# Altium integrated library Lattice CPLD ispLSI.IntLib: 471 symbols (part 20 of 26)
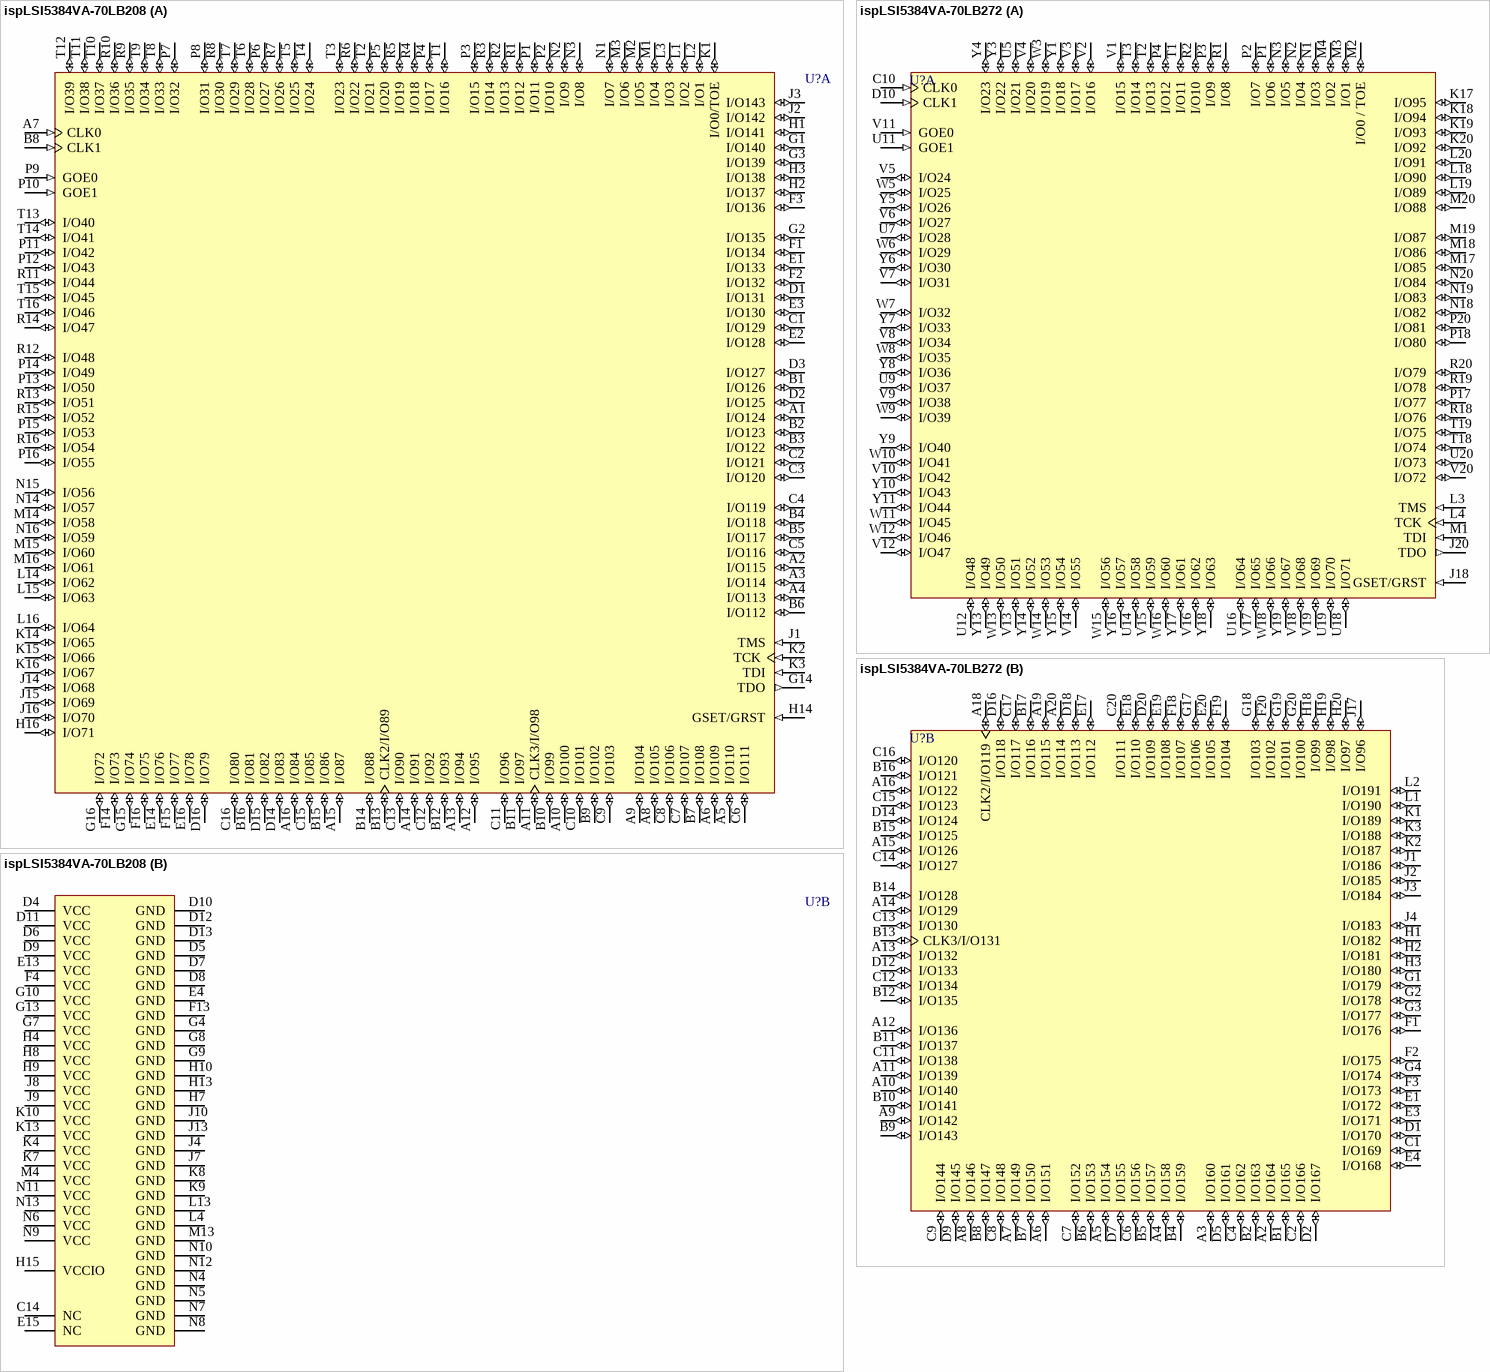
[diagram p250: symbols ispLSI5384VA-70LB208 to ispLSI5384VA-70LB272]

## ispLSI5384VA-70LB208
designator U?
In-System Programmable 3.3V SuperWIDE High Density PLD
footprint fpBGA208 (BGA, 208-Leads, Body 17x17mm, Pitch 1mm)
3D model 5256VA-fpBGA208 (208-Ball Fine Pitch Ball Grid Array (fpBGA208))
part A pins: A1 I/O124 (io), A2 I/O115 (io), A3 I/O114 (io), A4 I/O113 (io), A5 I/O110 (io), A6 I/O109 (io), A7 CLK0 (in), A8 I/O105 (io), A9 I/O104 (io), A10 I/O100 (io), A11 CLK3/I/O98 (io), A12 I/O95 (io), A13 I/O94 (io), A14 I/O91 (io), A15 I/O87 (io), A16 I/O84 (io), B1 I/O126 (io), B2 I/O123 (io), B3 I/O122 (io), B4 I/O118 (io), B5 I/O117 (io), B6 I/O112 (io), B7 I/O108 (io), B8 CLK1 (in), B9 I/O102 (io), B10 I/O99 (io), B11 I/O97 (io), B12 I/O93 (io), B13 CLK2/I/O89 (io), B14 I/O88 (io), B15 I/O86 (io), B16 I/O81 (io), C1 I/O129 (io), C2 I/O121 (io), C3 I/O120 (io), C4 I/O119 (io), C5 I/O116 (io), C6 I/O111 (io), C7 I/O107 (io), C8 I/O106 (io), C9 I/O103 (io), C10 I/O101 (io), C11 I/O96 (io), C12 I/O92 (io), C13 I/O90 (io), C15 I/O85 (io), C16 I/O80 (io), D1 I/O131 (io), D2 I/O125 (io), D3 I/O127 (io), D14 I/O83 (io), D15 I/O82 (io), D16 I/O79 (io), E1 I/O133 (io), E2 I/O128 (io), E3 I/O130 (io), E14 I/O76 (io), E16 I/O78 (io), F1 I/O134 (io), F2 I/O132 (io), F3 I/O136 (io), F14 I/O73 (io), F15 I/O77 (io), F16 I/O75 (io), G1 I/O140 (io), G2 I/O135 (io), G3 I/O139 (io), G14 TDO (out), G15 I/O74 (io), G16 I/O72 (io), H1 I/O141 (io), H2 I/O137 (io), H3 I/O138 (io), H14 GSET/GRST (in), H16 I/O71 (io), J1 TMS (in), J2 I/O142 (io), J3 I/O143 (io), J14 I/O68 (io), J15 I/O69 (io), J16 I/O70 (io), K1 I/O0/TOE (io), K2 TCK (in), K3 TDI (in), K14 I/O65 (io), K15 I/O66 (io), K16 I/O67 (io), L1 I/O2 (io), L2 I/O1 (io), L3 I/O3 (io), L14 I/O62 (io), L15 I/O63 (io), L16 I/O64 (io), M1 I/O4 (io), M2 I/O5 (io), M3 I/O6 (io), M14 I/O58 (io), M15 I/O60 (io), M16 I/O61 (io), N1 I/O7 (io), N2 I/O9 (io), N3 I/O8 (io), N14 I/O57 (io), N15 I/O56 (io), N16 I/O59 (io), P1 I/O11 (io), P2 I/O10 (io), P3 I/O15 (io), P4 I/O17 (io), P5 I/O20 (io), P6 I/O27 (io), P7 I/O32 (io), P8 I/O31 (io), P9 GOE0 (in), P10 GOE1 (in), P11 I/O42 (io), P12 I/O43 (io), P13 I/O50 (io), P14 I/O49 (io), P15 I/O53 (io), P16 I/O55 (io), R1 I/O12 (io), R2 I/O13 (io), R3 I/O14 (io), R4 I/O18 (io), R5 I/O19 (io), R6 I/O22 (io), R7 I/O26 (io), R8 I/O30 (io), R9 I/O35 (io), R10 I/O36 (io), R11 I/O44 (io), R12 I/O48 (io), R13 I/O51 (io), R14 I/O47 (io), R15 I/O52 (io), R16 I/O54 (io), T1 I/O16 (io), T2 I/O21 (io), T3 I/O23 (io), T4 I/O24 (io), T5 I/O25 (io), T6 I/O28 (io), T7 I/O29 (io), T8 I/O33 (io), T9 I/O34 (io), T10 I/O37 (io), T11 I/O38 (io), T12 I/O39 (io), T13 I/O40 (io), T14 I/O41 (io), T15 I/O45 (io), T16 I/O46 (io)
part B pins: C14 NC, D4 VCC (power), D5 GND (power), D6 VCC (power), D7 GND (power), D8 GND (power), D9 VCC (power), D10 GND (power), D11 VCC (power), D12 GND (power), D13 GND (power), E4 GND (power), E13 VCC (power), E15 NC, F4 VCC (power), F13 GND (power), G4 GND (power), G7 VCC (power), G8 GND (power), G9 GND (power), G10 VCC (power), G13 VCC (power), H4 VCC (power), H7 GND (power), H8 VCC (power), H9 VCC (power), H10 GND (power), H13 GND (power), H15 VCCIO (power), J4 GND (power), J7 GND (power), J8 VCC (power), J9 VCC (power), J10 GND (power), J13 GND (power), K4 VCC (power), K7 VCC (power), K8 GND (power), K9 GND (power), K10 VCC (power), K13 VCC (power), L4 GND (power), L13 GND (power), M4 VCC (power), M13 GND (power), N4 GND (power), N5 GND (power), N6 VCC (power), N7 GND (power), N8 GND (power), N9 VCC (power), N10 GND (power), N11 VCC (power), N12 GND (power), N13 VCC (power)

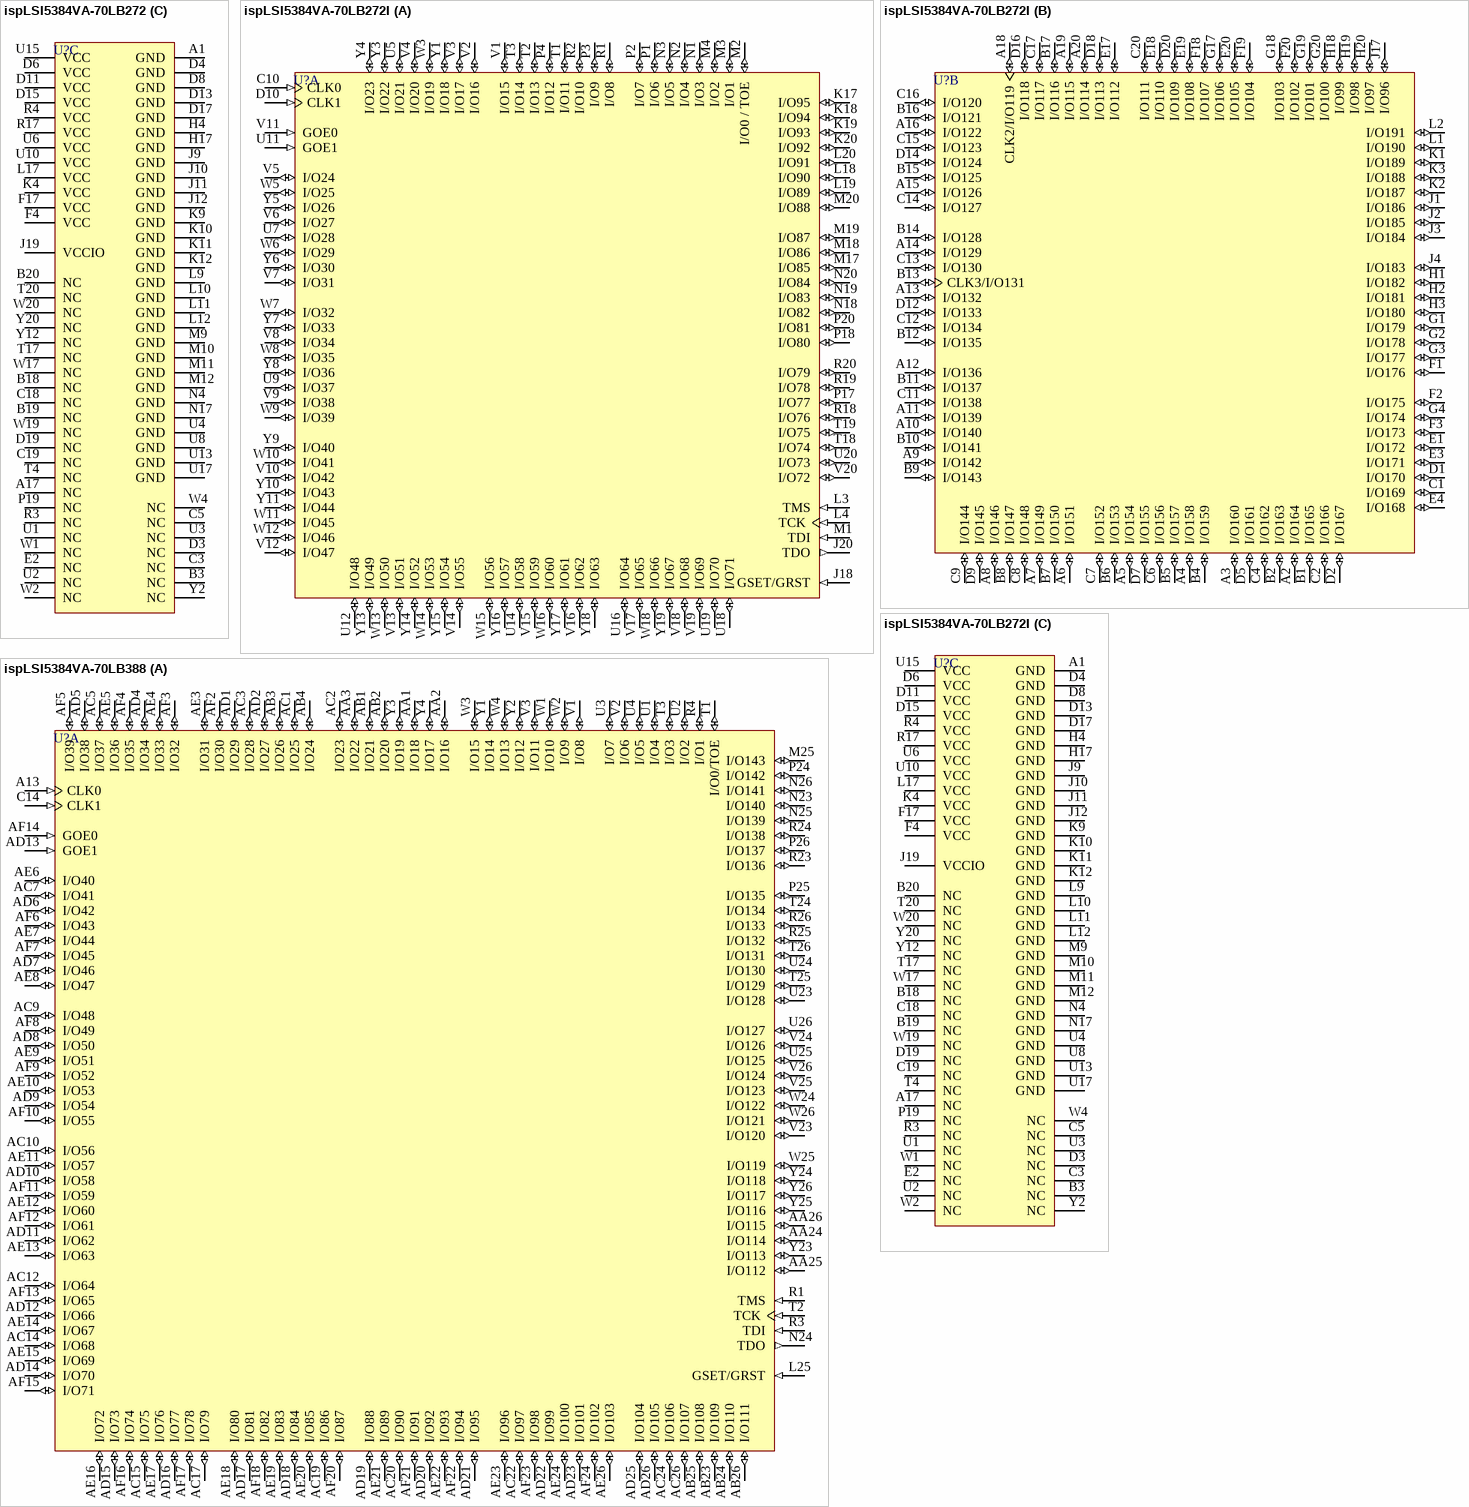
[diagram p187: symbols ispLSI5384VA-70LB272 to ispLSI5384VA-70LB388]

## ispLSI5384VA-70LB272
designator U?
In-System Programmable 3.3V SuperWIDE High Density PLD
footprint BGA272 (BGA, 272-Leads, Body 27x27mm, Pitch 1.27mm)
3D model 5384VA-BGA272 (272-Ball Ball Grid Array (BGA272))
part A pins: C10 CLK0 (in), D10 CLK1 (in), J18 GSET/GRST (in), J20 TDO (out), K17 I/O95 (io), K18 I/O94 (io), K19 I/O93 (io), K20 I/O92 (io), L3 TMS (in), L4 TCK (in), L18 I/O90 (io), L19 I/O89 (io), L20 I/O91 (io), M1 TDI (in), M2 I/O0 / TOE (io), M3 I/O1 (io), M4 I/O2 (io), M17 I/O85 (io), M18 I/O86 (io), M19 I/O87 (io), M20 I/O88 (io), N1 I/O3 (io), N2 I/O4 (io), N3 I/O5 (io), N18 I/O82 (io), N19 I/O83 (io), N20 I/O84 (io), P1 I/O6 (io), P2 I/O7 (io), P3 I/O9 (io), P4 I/O12 (io), P17 I/O77 (io), P18 I/O80 (io), P20 I/O81 (io), R1 I/O8 (io), R2 I/O10 (io), R18 I/O76 (io), R19 I/O78 (io), R20 I/O79 (io), T1 I/O11 (io), T2 I/O13 (io), T3 I/O14 (io), T18 I/O74 (io), T19 I/O75 (io), U5 I/O21 (io), U7 I/O28 (io), U9 I/O37 (io), U11 GOE1 (in), U12 I/O48 (io), U14 I/O58 (io), U16 I/O64 (io), U18 I/O71 (io), U19 I/O70 (io), U20 I/O73 (io), V1 I/O15 (io), V2 I/O16 (io), V3 I/O17 (io), V4 I/O20 (io), V5 I/O24 (io), V6 I/O27 (io), V7 I/O31 (io), V8 I/O34 (io), V9 I/O38 (io), V10 I/O42 (io), V11 GOE0 (in), V12 I/O47 (io), V13 I/O51 (io), V14 I/O55 (io), V15 I/O59 (io), V16 I/O62 (io), V17 I/O65 (io), V18 I/O68 (io), V19 I/O69 (io), V20 I/O72 (io), W3 I/O19 (io), W5 I/O25 (io), W6 I/O29 (io), W7 I/O32 (io), W8 I/O35 (io), W9 I/O39 (io), W10 I/O41 (io), W11 I/O45 (io), W12 I/O46 (io), W13 I/O50 (io), W14 I/O53 (io), W15 I/O56 (io), W16 I/O60 (io), W18 I/O66 (io), Y1 I/O18 (io), Y3 I/O22 (io), Y4 I/O23 (io), Y5 I/O26 (io), Y6 I/O30 (io), Y7 I/O33 (io), Y8 I/O36 (io), Y9 I/O40 (io), Y10 I/O43 (io), Y11 I/O44 (io), Y13 I/O49 (io), Y14 I/O52 (io), Y15 I/O54 (io), Y16 I/O57 (io), Y17 I/O61 (io), Y18 I/O63 (io), Y19 I/O67 (io)
part B pins: A2 I/O164 (io), A3 I/O160 (io), A4 I/O158 (io), A5 I/O154 (io), A6 I/O151 (io), A7 I/O149 (io), A8 I/O146 (io), A9 I/O142 (io), A10 I/O140 (io), A11 I/O139 (io), A12 I/O136 (io), A13 I/O132 (io), A14 I/O129 (io), A15 I/O126 (io), A16 I/O122 (io), A18 CLK2/I/O119 (io), A19 I/O115 (io), A20 I/O114 (io), B1 I/O165 (io), B2 I/O163 (io), B4 I/O159 (io), B5 I/O157 (io), B6 I/O153 (io), B7 I/O150 (io), B8 I/O147 (io), B9 I/O143 (io), B10 I/O141 (io), B11 I/O137 (io), B12 I/O135 (io), B13 CLK3/I/O131 (io), B14 I/O128 (io), B15 I/O125 (io), B16 I/O121 (io), B17 I/O116 (io), C1 I/O169 (io), C2 I/O166 (io), C4 I/O162 (io), C6 I/O156 (io), C7 I/O152 (io), C8 I/O148 (io), C9 I/O144 (io), C11 I/O138 (io), C12 I/O134 (io), C13 I/O130 (io), C14 I/O127 (io), C15 I/O123 (io), C16 I/O120 (io), C17 I/O117 (io), C20 I/O111 (io), D1 I/O170 (io), D2 I/O167 (io), D5 I/O161 (io), D7 I/O155 (io), D9 I/O145 (io), D12 I/O133 (io), D14 I/O124 (io), D16 I/O118 (io), D18 I/O113 (io), D20 I/O109 (io), E1 I/O172 (io), E3 I/O171 (io), E4 I/O168 (io), E17 I/O112 (io), E18 I/O110 (io), E19 I/O108 (io), E20 I/O105 (io), F1 I/O176 (io), F2 I/O175 (io), F3 I/O173 (io), F18 I/O107 (io), F19 I/O104 (io), F20 I/O102 (io), G1 I/O179 (io), G2 I/O178 (io), G3 I/O177 (io), G4 I/O174 (io), G17 I/O106 (io), G18 I/O103 (io), G19 I/O101 (io), G20 I/O100 (io), H1 I/O182 (io), H2 I/O181 (io), H3 I/O180 (io), H18 I/O99 (io), H19 I/O98 (io), H20 I/O97 (io), J1 I/O186 (io), J2 I/O185 (io), J3 I/O184 (io), J4 I/O183 (io), J17 I/O96 (io), K1 I/O189 (io), K2 I/O187 (io), K3 I/O188 (io), L1 I/O190 (io), L2 I/O191 (io)
part C pins: A1 GND (power), A17 NC, B3 NC, B18 NC, B19 NC, B20 NC, C3 NC, C5 NC, C18 NC, C19 NC, D3 NC, D4 GND (power), D6 VCC (power), D8 GND (power), D11 VCC (power), D13 GND (power), D15 VCC (power), D17 GND (power), D19 NC, E2 NC, F4 VCC (power), F17 VCC (power), H4 GND (power), H17 GND (power), J9 GND (power), J10 GND (power), J11 GND (power), J12 GND (power), J19 VCCIO (power), K4 VCC (power), K9 GND (power), K10 GND (power), K11 GND (power), K12 GND (power), L9 GND (power), L10 GND (power), L11 GND (power), L12 GND (power), L17 VCC (power), M9 GND (power), M10 GND (power), M11 GND (power), M12 GND (power), N4 GND (power), N17 GND (power), P19 NC, R3 NC, R4 VCC (power), R17 VCC (power), T4 NC, T17 NC, T20 NC, U1 NC, U2 NC, U3 NC, U4 GND (power), U6 VCC (power), U8 GND (power), U10 VCC (power), U13 GND (power), U15 VCC (power), U17 GND (power), W1 NC, W2 NC, W4 NC, W17 NC, W19 NC, W20 NC, Y2 NC, Y12 NC, Y20 NC

## ispLSI5384VA-70LB272I
designator U?
In-System Programmable 3.3V SuperWIDE High Density PLD
footprint BGA272 (BGA, 272-Leads, Body 27x27mm, Pitch 1.27mm)
3D model 5384VA-BGA272 (272-Ball Ball Grid Array (BGA272))
part A pins: C10 CLK0 (in), D10 CLK1 (in), J18 GSET/GRST (in), J20 TDO (out), K17 I/O95 (io), K18 I/O94 (io), K19 I/O93 (io), K20 I/O92 (io), L3 TMS (in), L4 TCK (in), L18 I/O90 (io), L19 I/O89 (io), L20 I/O91 (io), M1 TDI (in), M2 I/O0 / TOE (io), M3 I/O1 (io), M4 I/O2 (io), M17 I/O85 (io), M18 I/O86 (io), M19 I/O87 (io), M20 I/O88 (io), N1 I/O3 (io), N2 I/O4 (io), N3 I/O5 (io), N18 I/O82 (io), N19 I/O83 (io), N20 I/O84 (io), P1 I/O6 (io), P2 I/O7 (io), P3 I/O9 (io), P4 I/O12 (io), P17 I/O77 (io), P18 I/O80 (io), P20 I/O81 (io), R1 I/O8 (io), R2 I/O10 (io), R18 I/O76 (io), R19 I/O78 (io), R20 I/O79 (io), T1 I/O11 (io), T2 I/O13 (io), T3 I/O14 (io), T18 I/O74 (io), T19 I/O75 (io), U5 I/O21 (io), U7 I/O28 (io), U9 I/O37 (io), U11 GOE1 (in), U12 I/O48 (io), U14 I/O58 (io), U16 I/O64 (io), U18 I/O71 (io), U19 I/O70 (io), U20 I/O73 (io), V1 I/O15 (io), V2 I/O16 (io), V3 I/O17 (io), V4 I/O20 (io), V5 I/O24 (io), V6 I/O27 (io), V7 I/O31 (io), V8 I/O34 (io), V9 I/O38 (io), V10 I/O42 (io), V11 GOE0 (in), V12 I/O47 (io), V13 I/O51 (io), V14 I/O55 (io), V15 I/O59 (io), V16 I/O62 (io), V17 I/O65 (io), V18 I/O68 (io), V19 I/O69 (io), V20 I/O72 (io), W3 I/O19 (io), W5 I/O25 (io), W6 I/O29 (io), W7 I/O32 (io), W8 I/O35 (io), W9 I/O39 (io), W10 I/O41 (io), W11 I/O45 (io), W12 I/O46 (io), W13 I/O50 (io), W14 I/O53 (io), W15 I/O56 (io), W16 I/O60 (io), W18 I/O66 (io), Y1 I/O18 (io), Y3 I/O22 (io), Y4 I/O23 (io), Y5 I/O26 (io), Y6 I/O30 (io), Y7 I/O33 (io), Y8 I/O36 (io), Y9 I/O40 (io), Y10 I/O43 (io), Y11 I/O44 (io), Y13 I/O49 (io), Y14 I/O52 (io), Y15 I/O54 (io), Y16 I/O57 (io), Y17 I/O61 (io), Y18 I/O63 (io), Y19 I/O67 (io)
part B pins: A2 I/O164 (io), A3 I/O160 (io), A4 I/O158 (io), A5 I/O154 (io), A6 I/O151 (io), A7 I/O149 (io), A8 I/O146 (io), A9 I/O142 (io), A10 I/O140 (io), A11 I/O139 (io), A12 I/O136 (io), A13 I/O132 (io), A14 I/O129 (io), A15 I/O126 (io), A16 I/O122 (io), A18 CLK2/I/O119 (io), A19 I/O115 (io), A20 I/O114 (io), B1 I/O165 (io), B2 I/O163 (io), B4 I/O159 (io), B5 I/O157 (io), B6 I/O153 (io), B7 I/O150 (io), B8 I/O147 (io), B9 I/O143 (io), B10 I/O141 (io), B11 I/O137 (io), B12 I/O135 (io), B13 CLK3/I/O131 (io), B14 I/O128 (io), B15 I/O125 (io), B16 I/O121 (io), B17 I/O116 (io), C1 I/O169 (io), C2 I/O166 (io), C4 I/O162 (io), C6 I/O156 (io), C7 I/O152 (io), C8 I/O148 (io), C9 I/O144 (io), C11 I/O138 (io), C12 I/O134 (io), C13 I/O130 (io), C14 I/O127 (io), C15 I/O123 (io), C16 I/O120 (io), C17 I/O117 (io), C20 I/O111 (io), D1 I/O170 (io), D2 I/O167 (io), D5 I/O161 (io), D7 I/O155 (io), D9 I/O145 (io), D12 I/O133 (io), D14 I/O124 (io), D16 I/O118 (io), D18 I/O113 (io), D20 I/O109 (io), E1 I/O172 (io), E3 I/O171 (io), E4 I/O168 (io), E17 I/O112 (io), E18 I/O110 (io), E19 I/O108 (io), E20 I/O105 (io), F1 I/O176 (io), F2 I/O175 (io), F3 I/O173 (io), F18 I/O107 (io), F19 I/O104 (io), F20 I/O102 (io), G1 I/O179 (io), G2 I/O178 (io), G3 I/O177 (io), G4 I/O174 (io), G17 I/O106 (io), G18 I/O103 (io), G19 I/O101 (io), G20 I/O100 (io), H1 I/O182 (io), H2 I/O181 (io), H3 I/O180 (io), H18 I/O99 (io), H19 I/O98 (io), H20 I/O97 (io), J1 I/O186 (io), J2 I/O185 (io), J3 I/O184 (io), J4 I/O183 (io), J17 I/O96 (io), K1 I/O189 (io), K2 I/O187 (io), K3 I/O188 (io), L1 I/O190 (io), L2 I/O191 (io)
part C pins: A1 GND (power), A17 NC, B3 NC, B18 NC, B19 NC, B20 NC, C3 NC, C5 NC, C18 NC, C19 NC, D3 NC, D4 GND (power), D6 VCC (power), D8 GND (power), D11 VCC (power), D13 GND (power), D15 VCC (power), D17 GND (power), D19 NC, E2 NC, F4 VCC (power), F17 VCC (power), H4 GND (power), H17 GND (power), J9 GND (power), J10 GND (power), J11 GND (power), J12 GND (power), J19 VCCIO (power), K4 VCC (power), K9 GND (power), K10 GND (power), K11 GND (power), K12 GND (power), L9 GND (power), L10 GND (power), L11 GND (power), L12 GND (power), L17 VCC (power), M9 GND (power), M10 GND (power), M11 GND (power), M12 GND (power), N4 GND (power), N17 GND (power), P19 NC, R3 NC, R4 VCC (power), R17 VCC (power), T4 NC, T17 NC, T20 NC, U1 NC, U2 NC, U3 NC, U4 GND (power), U6 VCC (power), U8 GND (power), U10 VCC (power), U13 GND (power), U15 VCC (power), U17 GND (power), W1 NC, W2 NC, W4 NC, W17 NC, W19 NC, W20 NC, Y2 NC, Y12 NC, Y20 NC

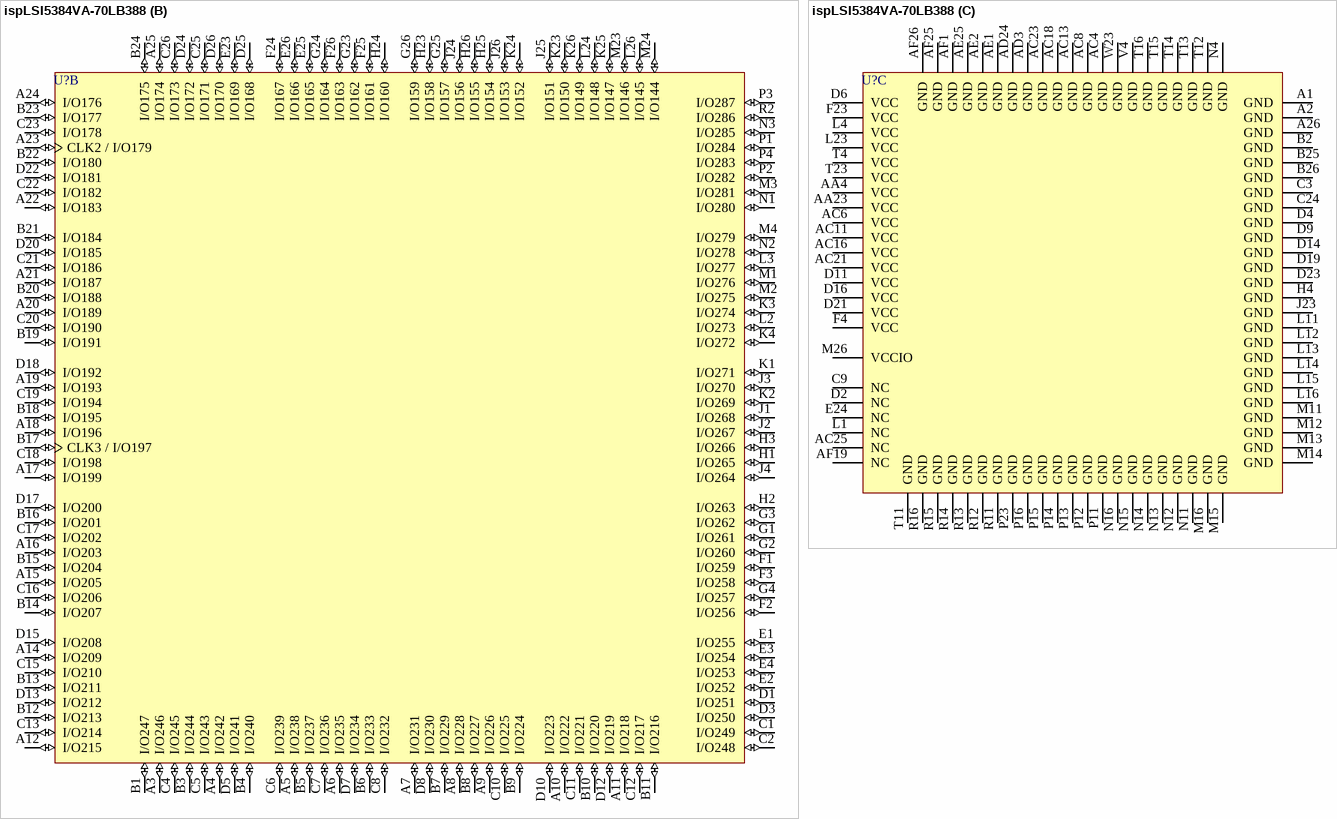
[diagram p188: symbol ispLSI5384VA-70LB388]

## ispLSI5384VA-70LB388
designator U?
In-System Programmable 3.3V SuperWIDE High Density PLD
footprint BGA388 (BGA, 388-Leads, Body 35x35mm, Pitch 1.27mm)
3D model 5384VA-BGA388 (388-Ball Ball Grid Array (BGA388))
part A pins: A13 CLK0 (in), AA1 I/O18 (io), AA2 I/O16 (io), AA3 I/O22 (io), AA24 I/O114 (io), AA25 I/O112 (io), AA26 I/O115 (io), AB1 I/O21 (io), AB2 I/O20 (io), AB3 I/O26 (io), AB4 I/O24 (io), AB23 I/O109 (io), AB24 I/O110 (io), AB25 I/O108 (io), AB26 I/O111 (io), AC1 I/O25 (io), AC2 I/O23 (io), AC3 I/O28 (io), AC5 I/O37 (io), AC7 I/O41 (io), AC9 I/O48 (io), AC10 I/O56 (io), AC12 I/O64 (io), AC14 I/O68 (io), AC15 I/O75 (io), AC17 I/O79 (io), AC19 I/O86 (io), AC20 I/O90 (io), AC22 I/O97 (io), AC24 I/O106 (io), AC26 I/O107 (io), AD1 I/O29 (io), AD2 I/O27 (io), AD4 I/O34 (io), AD5 I/O38 (io), AD6 I/O42 (io), AD7 I/O46 (io), AD8 I/O50 (io), AD9 I/O54 (io), AD10 I/O58 (io), AD11 I/O62 (io), AD12 I/O66 (io), AD13 GOE1 (in), AD14 I/O70 (io), AD15 I/O73 (io), AD16 I/O77 (io), AD17 I/O81 (io), AD18 I/O84 (io), AD19 I/O88 (io), AD20 I/O92 (io), AD21 I/O95 (io), AD22 I/O99 (io), AD23 I/O101 (io), AD25 I/O104 (io), AD26 I/O105 (io), AE3 I/O31 (io), AE4 I/O33 (io), AE5 I/O36 (io), AE6 I/O40 (io), AE7 I/O44 (io), AE8 I/O47 (io), AE9 I/O51 (io), AE10 I/O53 (io), AE11 I/O57 (io), AE12 I/O60 (io), AE13 I/O63 (io), AE14 I/O67 (io), AE15 I/O69 (io), AE16 I/O72 (io), AE17 I/O76 (io), AE18 I/O80 (io), AE19 I/O83 (io), AE20 I/O85 (io), AE21 I/O89 (io), AE22 I/O93 (io), AE23 I/O96 (io), AE24 I/O100 (io), AE26 I/O103 (io), AF2 I/O30 (io), AF3 I/O32 (io), AF4 I/O35 (io), AF5 I/O39 (io), AF6 I/O43 (io), AF7 I/O45 (io), AF8 I/O49 (io), AF9 I/O52 (io), AF10 I/O55 (io), AF11 I/O59 (io), AF12 I/O61 (io), AF13 I/O65 (io), AF14 GOE0 (in), AF15 I/O71 (io), AF16 I/O74 (io), AF17 I/O78 (io), AF18 I/O82 (io), AF20 I/O87 (io), AF21 I/O91 (io), AF22 I/O94 (io), AF23 I/O98 (io), AF24 I/O102 (io), C14 CLK1 (in), L25 GSET/GRST (in), M25 I/O143 (io), N23 I/O140 (io), N24 TDO (out), N25 I/O139 (io), N26 I/O141 (io), P24 I/O142 (io), P25 I/O135 (io), P26 I/O137 (io), R1 TMS (in), R3 TDI (in), R4 I/O1 (io), R23 I/O136 (io), R24 I/O138 (io), R25 I/O132 (io), R26 I/O133 (io), T1 I/O0/TOE (io), T2 TCK (in), T3 I/O3 (io), T24 I/O134 (io), T25 I/O129 (io), T26 I/O131 (io), U1 I/O4 (io), U2 I/O2 (io), U3 I/O7 (io), U4 I/O5 (io), U23 I/O128 (io), U24 I/O130 (io), U25 I/O125 (io), U26 I/O127 (io), V1 I/O8 (io), V2 I/O6 (io), V3 I/O11 (io), V23 I/O120 (io), V24 I/O126 (io), V25 I/O123 (io), V26 I/O124 (io), W1 I/O10 (io), W2 I/O9 (io), W3 I/O15 (io), W4 I/O13 (io), W24 I/O122 (io), W25 I/O119 (io), W26 I/O121 (io), Y1 I/O14 (io), Y2 I/O12 (io), Y3 I/O19 (io), Y4 I/O17 (io), Y23 I/O113 (io), Y24 I/O118 (io), Y25 I/O116 (io), Y26 I/O117 (io)
part B pins: A3 I/O246 (io), A4 I/O242 (io), A5 I/O238 (io), A6 I/O235 (io), A7 I/O231 (io), A8 I/O228 (io), A9 I/O226 (io), A10 I/O222 (io), A11 I/O218 (io), A12 I/O215 (io), A14 I/O209 (io), A15 I/O205 (io), A16 I/O203 (io), A17 I/O199 (io), A18 I/O196 (io), A19 I/O193 (io), A20 I/O189 (io), A21 I/O187 (io), A22 I/O183 (io), A23 CLK2 / I/O179 (io), A24 I/O176 (io), A25 I/O174 (io), B1 I/O247 (io), B3 I/O244 (io), B4 I/O240 (io), B5 I/O237 (io), B6 I/O233 (io), B7 I/O229 (io), B8 I/O227 (io), B9 I/O224 (io), B10 I/O220 (io), B11 I/O216 (io), B12 I/O213 (io), B13 I/O211 (io), B14 I/O207 (io), B15 I/O204 (io), B16 I/O201 (io), B17 CLK3 / I/O197 (io), B18 I/O195 (io), B19 I/O191 (io), B20 I/O188 (io), B21 I/O184 (io), B22 I/O180 (io), B23 I/O177 (io), B24 I/O175 (io), C1 I/O249 (io), C2 I/O248 (io), C4 I/O245 (io), C5 I/O243 (io), C6 I/O239 (io), C7 I/O236 (io), C8 I/O232 (io), C10 I/O225 (io), C11 I/O221 (io), C12 I/O217 (io), C13 I/O214 (io), C15 I/O210 (io), C16 I/O206 (io), C17 I/O202 (io), C18 I/O198 (io), C19 I/O194 (io), C20 I/O190 (io), C21 I/O186 (io), C22 I/O182 (io), C23 I/O178 (io), C25 I/O171 (io), C26 I/O173 (io), D1 I/O251 (io), D3 I/O250 (io), D5 I/O241 (io), D7 I/O234 (io), D8 I/O230 (io), D10 I/O223 (io), D12 I/O219 (io), D13 I/O212 (io), D15 I/O208 (io), D17 I/O200 (io), D18 I/O192 (io), D20 I/O185 (io), D22 I/O181 (io), D24 I/O172 (io), D25 I/O168 (io), D26 I/O170 (io), E1 I/O255 (io), E2 I/O252 (io), E3 I/O254 (io), E4 I/O253 (io), E23 I/O169 (io), E25 I/O165 (io), E26 I/O166 (io), F1 I/O259 (io), F2 I/O256 (io), F3 I/O258 (io), F24 I/O167 (io), F25 I/O161 (io), F26 I/O163 (io), G1 I/O261 (io), G2 I/O260 (io), G3 I/O262 (io), G4 I/O257 (io), G23 I/O162 (io), G24 I/O164 (io), G25 I/O157 (io), G26 I/O159 (io), H1 I/O265 (io), H2 I/O263 (io), H3 I/O266 (io), H23 I/O158 (io), H24 I/O160 (io), H25 I/O154 (io), H26 I/O155 (io), J1 I/O268 (io), J2 I/O267 (io), J3 I/O270 (io), J4 I/O264 (io), J24 I/O156 (io), J25 I/O151 (io), J26 I/O153 (io), K1 I/O271 (io), K2 I/O269 (io), K3 I/O274 (io), K4 I/O272 (io), K23 I/O150 (io), K24 I/O152 (io), K25 I/O147 (io), K26 I/O149 (io), L2 I/O273 (io), L3 I/O277 (io), L24 I/O148 (io), L26 I/O145 (io), M1 I/O276 (io), M2 I/O275 (io), M3 I/O281 (io), M4 I/O279 (io), M23 I/O146 (io), M24 I/O144 (io), N1 I/O280 (io), N2 I/O278 (io), N3 I/O285 (io), P1 I/O284 (io), P2 I/O282 (io), P3 I/O287 (io), P4 I/O283 (io), R2 I/O286 (io)
part C pins: A1 GND (power), A2 GND (power), A26 GND (power), AA4 VCC (power), AA23 VCC (power), AC4 GND (power), AC6 VCC (power), AC8 GND (power), AC11 VCC (power), AC13 GND (power), AC16 VCC (power), AC18 GND (power), AC21 VCC (power), AC23 GND (power), AC25 NC, AD3 GND (power), AD24 GND (power), AE1 GND (power), AE2 GND (power), AE25 GND (power), AF1 GND (power), AF19 NC, AF25 GND (power), AF26 GND (power), B2 GND (power), B25 GND (power), B26 GND (power), C3 GND (power), C9 NC, C24 GND (power), D2 NC, D4 GND (power), D6 VCC (power), D9 GND (power), D11 VCC (power), D14 GND (power), D16 VCC (power), D19 GND (power), D21 VCC (power), D23 GND (power), E24 NC, F4 VCC (power), F23 VCC (power), H4 GND (power), J23 GND (power), L1 NC, L4 VCC (power), L11 GND (power), L12 GND (power), L13 GND (power), L14 GND (power), L15 GND (power), L16 GND (power), L23 VCC (power), M11 GND (power), M12 GND (power), M13 GND (power), M14 GND (power), M15 GND (power), M16 GND (power), M26 VCCIO (power), N4 GND (power), N11 GND (power), N12 GND (power), N13 GND (power), N14 GND (power), N15 GND (power), N16 GND (power), P11 GND (power), P12 GND (power), P13 GND (power), P14 GND (power), P15 GND (power), P16 GND (power), P23 GND (power), R11 GND (power), R12 GND (power), R13 GND (power), R14 GND (power), R15 GND (power), R16 GND (power), T4 VCC (power), T11 GND (power), T12 GND (power), T13 GND (power), T14 GND (power), T15 GND (power), T16 GND (power), T23 VCC (power), V4 GND (power), W23 GND (power)

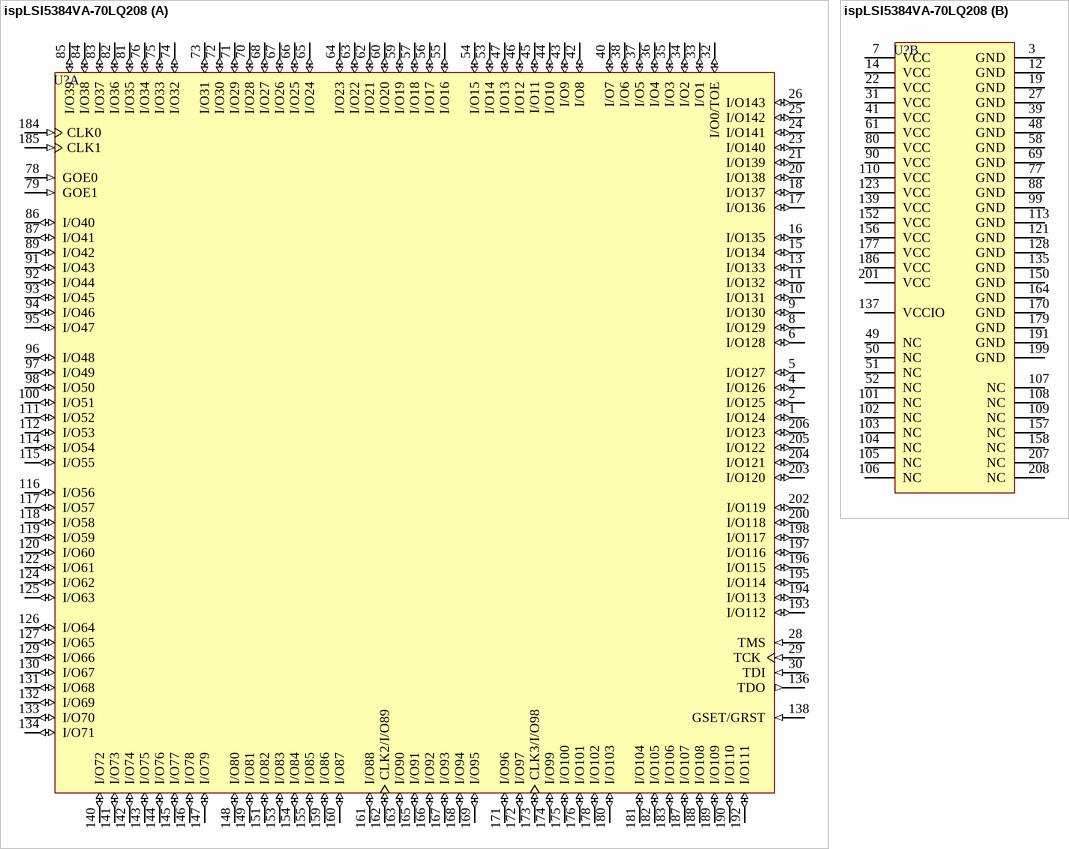
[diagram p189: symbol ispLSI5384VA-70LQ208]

## ispLSI5384VA-70LQ208
designator U?
In-System Programmable 3.3V SuperWIDE High Density PLD
footprint PQFP208_N (Shrink QFP, 208-Leads, Body 28x28mm, Pitch 0.5mm, IPC Medium Density)
footprint PQFP208_L (Shrink QFP, 208-Leads, Body 28x28mm, Pitch 0.5mm, IPC High Density)
footprint PQFP208_M (Shrink QFP, 208-Leads, Body 28x28mm, Pitch 0.5mm, IPC Low Density)
3D model 5384VA-PQFP208 (208-Pin Plastic Quad Flat Pack (PQFP208))
part A pins: 1 I/O124 (io), 2 I/O125 (io), 4 I/O126 (io), 5 I/O127 (io), 6 I/O128 (io), 8 I/O129 (io), 9 I/O130 (io), 10 I/O131 (io), 11 I/O132 (io), 13 I/O133 (io), 15 I/O134 (io), 16 I/O135 (io), 17 I/O136 (io), 18 I/O137 (io), 20 I/O138 (io), 21 I/O139 (io), 23 I/O140 (io), 24 I/O141 (io), 25 I/O142 (io), 26 I/O143 (io), 28 TMS (in), 29 TCK (in), 30 TDI (in), 32 I/O0/TOE (io), 33 I/O1 (io), 34 I/O2 (io), 35 I/O3 (io), 36 I/O4 (io), 37 I/O5 (io), 38 I/O6 (io), 40 I/O7 (io), 42 I/O8 (io), 43 I/O9 (io), 44 I/O10 (io), 45 I/O11 (io), 46 I/O12 (io), 47 I/O13 (io), 53 I/O14 (io), 54 I/O15 (io), 55 I/O16 (io), 56 I/O17 (io), 57 I/O18 (io), 59 I/O19 (io), 60 I/O20 (io), 62 I/O21 (io), 63 I/O22 (io), 64 I/O23 (io), 65 I/O24 (io), 66 I/O25 (io), 67 I/O26 (io), 68 I/O27 (io), 70 I/O28 (io), 71 I/O29 (io), 72 I/O30 (io), 73 I/O31 (io), 74 I/O32 (io), 75 I/O33 (io), 76 I/O34 (io), 78 GOE0 (in), 79 GOE1 (in), 81 I/O35 (io), 82 I/O36 (io), 83 I/O37 (io), 84 I/O38 (io), 85 I/O39 (io), 86 I/O40 (io), 87 I/O41 (io), 89 I/O42 (io), 91 I/O43 (io), 92 I/O44 (io), 93 I/O45 (io), 94 I/O46 (io), 95 I/O47 (io), 96 I/O48 (io), 97 I/O49 (io), 98 I/O50 (io), 100 I/O51 (io), 111 I/O52 (io), 112 I/O53 (io), 114 I/O54 (io), 115 I/O55 (io), 116 I/O56 (io), 117 I/O57 (io), 118 I/O58 (io), 119 I/O59 (io), 120 I/O60 (io), 122 I/O61 (io), 124 I/O62 (io), 125 I/O63 (io), 126 I/O64 (io), 127 I/O65 (io), 129 I/O66 (io), 130 I/O67 (io), 131 I/O68 (io), 132 I/O69 (io), 133 I/O70 (io), 134 I/O71 (io), 136 TDO (out), 138 GSET/GRST (in), 140 I/O72 (io), 141 I/O73 (io), 142 I/O74 (io), 143 I/O75 (io), 144 I/O76 (io), 145 I/O77 (io), 146 I/O78 (io), 147 I/O79 (io), 148 I/O80 (io), 149 I/O81 (io), 151 I/O82 (io), 153 I/O83 (io), 154 I/O84 (io), 155 I/O85 (io), 159 I/O86 (io), 160 I/O87 (io), 161 I/O88 (io), 162 CLK2/I/O89 (io), 163 I/O90 (io), 165 I/O91 (io), 166 I/O92 (io), 167 I/O93 (io), 168 I/O94 (io), 169 I/O95 (io), 171 I/O96 (io), 172 I/O97 (io), 173 CLK3/I/O98 (io), 174 I/O99 (io), 175 I/O100 (io), 176 I/O101 (io), 178 I/O102 (io), 180 I/O103 (io), 181 I/O104 (io), 182 I/O105 (io), 183 I/O106 (io), 184 CLK0 (in), 185 CLK1 (in), 187 I/O107 (io), 188 I/O108 (io), 189 I/O109 (io), 190 I/O110 (io), 192 I/O111 (io), 193 I/O112 (io), 194 I/O113 (io), 195 I/O114 (io), 196 I/O115 (io), 197 I/O116 (io), 198 I/O117 (io), 200 I/O118 (io), 202 I/O119 (io), 203 I/O120 (io), 204 I/O121 (io), 205 I/O122 (io), 206 I/O123 (io)
part B pins: 3 GND (power), 7 VCC (power), 12 GND (power), 14 VCC (power), 19 GND (power), 22 VCC (power), 27 GND (power), 31 VCC (power), 39 GND (power), 41 VCC (power), 48 GND (power), 49 NC, 50 NC, 51 NC, 52 NC, 58 GND (power), 61 VCC (power), 69 GND (power), 77 GND (power), 80 VCC (power), 88 GND (power), 90 VCC (power), 99 GND (power), 101 NC, 102 NC, 103 NC, 104 NC, 105 NC, 106 NC, 107 NC, 108 NC, 109 NC, 110 VCC (power), 113 GND (power), 121 GND (power), 123 VCC (power), 128 GND (power), 135 GND (power), 137 VCCIO (power), 139 VCC (power), 150 GND (power), 152 VCC (power), 156 VCC (power), 157 NC, 158 NC, 164 GND (power), 170 GND (power), 177 VCC (power), 179 GND (power), 186 VCC (power), 191 GND (power), 199 GND (power), 201 VCC (power), 207 NC, 208 NC

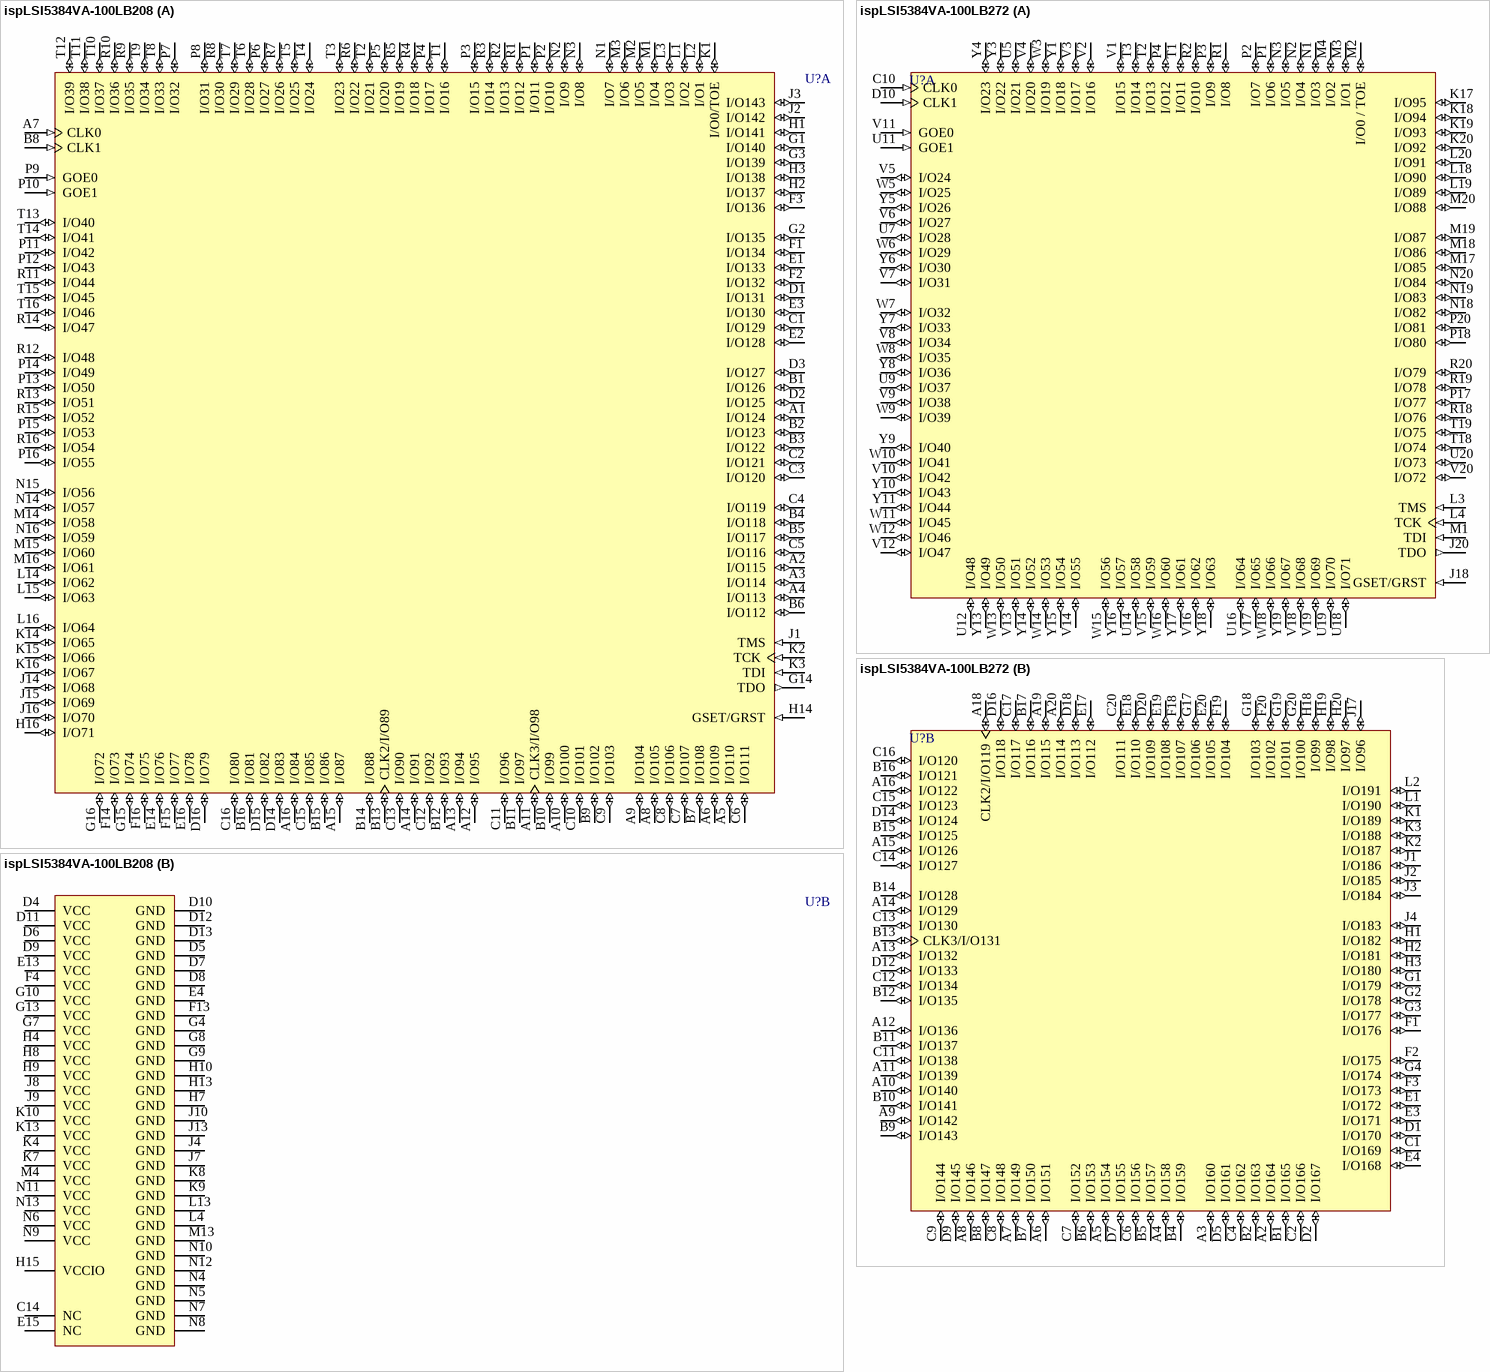
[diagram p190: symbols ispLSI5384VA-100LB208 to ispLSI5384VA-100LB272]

## ispLSI5384VA-100LB208
designator U?
In-System Programmable 3.3V SuperWIDE High Density PLD
footprint fpBGA208 (BGA, 208-Leads, Body 17x17mm, Pitch 1mm)
3D model 5256VA-fpBGA208 (208-Ball Fine Pitch Ball Grid Array (fpBGA208))
part A pins: A1 I/O124 (io), A2 I/O115 (io), A3 I/O114 (io), A4 I/O113 (io), A5 I/O110 (io), A6 I/O109 (io), A7 CLK0 (in), A8 I/O105 (io), A9 I/O104 (io), A10 I/O100 (io), A11 CLK3/I/O98 (io), A12 I/O95 (io), A13 I/O94 (io), A14 I/O91 (io), A15 I/O87 (io), A16 I/O84 (io), B1 I/O126 (io), B2 I/O123 (io), B3 I/O122 (io), B4 I/O118 (io), B5 I/O117 (io), B6 I/O112 (io), B7 I/O108 (io), B8 CLK1 (in), B9 I/O102 (io), B10 I/O99 (io), B11 I/O97 (io), B12 I/O93 (io), B13 CLK2/I/O89 (io), B14 I/O88 (io), B15 I/O86 (io), B16 I/O81 (io), C1 I/O129 (io), C2 I/O121 (io), C3 I/O120 (io), C4 I/O119 (io), C5 I/O116 (io), C6 I/O111 (io), C7 I/O107 (io), C8 I/O106 (io), C9 I/O103 (io), C10 I/O101 (io), C11 I/O96 (io), C12 I/O92 (io), C13 I/O90 (io), C15 I/O85 (io), C16 I/O80 (io), D1 I/O131 (io), D2 I/O125 (io), D3 I/O127 (io), D14 I/O83 (io), D15 I/O82 (io), D16 I/O79 (io), E1 I/O133 (io), E2 I/O128 (io), E3 I/O130 (io), E14 I/O76 (io), E16 I/O78 (io), F1 I/O134 (io), F2 I/O132 (io), F3 I/O136 (io), F14 I/O73 (io), F15 I/O77 (io), F16 I/O75 (io), G1 I/O140 (io), G2 I/O135 (io), G3 I/O139 (io), G14 TDO (out), G15 I/O74 (io), G16 I/O72 (io), H1 I/O141 (io), H2 I/O137 (io), H3 I/O138 (io), H14 GSET/GRST (in), H16 I/O71 (io), J1 TMS (in), J2 I/O142 (io), J3 I/O143 (io), J14 I/O68 (io), J15 I/O69 (io), J16 I/O70 (io), K1 I/O0/TOE (io), K2 TCK (in), K3 TDI (in), K14 I/O65 (io), K15 I/O66 (io), K16 I/O67 (io), L1 I/O2 (io), L2 I/O1 (io), L3 I/O3 (io), L14 I/O62 (io), L15 I/O63 (io), L16 I/O64 (io), M1 I/O4 (io), M2 I/O5 (io), M3 I/O6 (io), M14 I/O58 (io), M15 I/O60 (io), M16 I/O61 (io), N1 I/O7 (io), N2 I/O9 (io), N3 I/O8 (io), N14 I/O57 (io), N15 I/O56 (io), N16 I/O59 (io), P1 I/O11 (io), P2 I/O10 (io), P3 I/O15 (io), P4 I/O17 (io), P5 I/O20 (io), P6 I/O27 (io), P7 I/O32 (io), P8 I/O31 (io), P9 GOE0 (in), P10 GOE1 (in), P11 I/O42 (io), P12 I/O43 (io), P13 I/O50 (io), P14 I/O49 (io), P15 I/O53 (io), P16 I/O55 (io), R1 I/O12 (io), R2 I/O13 (io), R3 I/O14 (io), R4 I/O18 (io), R5 I/O19 (io), R6 I/O22 (io), R7 I/O26 (io), R8 I/O30 (io), R9 I/O35 (io), R10 I/O36 (io), R11 I/O44 (io), R12 I/O48 (io), R13 I/O51 (io), R14 I/O47 (io), R15 I/O52 (io), R16 I/O54 (io), T1 I/O16 (io), T2 I/O21 (io), T3 I/O23 (io), T4 I/O24 (io), T5 I/O25 (io), T6 I/O28 (io), T7 I/O29 (io), T8 I/O33 (io), T9 I/O34 (io), T10 I/O37 (io), T11 I/O38 (io), T12 I/O39 (io), T13 I/O40 (io), T14 I/O41 (io), T15 I/O45 (io), T16 I/O46 (io)
part B pins: C14 NC, D4 VCC (power), D5 GND (power), D6 VCC (power), D7 GND (power), D8 GND (power), D9 VCC (power), D10 GND (power), D11 VCC (power), D12 GND (power), D13 GND (power), E4 GND (power), E13 VCC (power), E15 NC, F4 VCC (power), F13 GND (power), G4 GND (power), G7 VCC (power), G8 GND (power), G9 GND (power), G10 VCC (power), G13 VCC (power), H4 VCC (power), H7 GND (power), H8 VCC (power), H9 VCC (power), H10 GND (power), H13 GND (power), H15 VCCIO (power), J4 GND (power), J7 GND (power), J8 VCC (power), J9 VCC (power), J10 GND (power), J13 GND (power), K4 VCC (power), K7 VCC (power), K8 GND (power), K9 GND (power), K10 VCC (power), K13 VCC (power), L4 GND (power), L13 GND (power), M4 VCC (power), M13 GND (power), N4 GND (power), N5 GND (power), N6 VCC (power), N7 GND (power), N8 GND (power), N9 VCC (power), N10 GND (power), N11 VCC (power), N12 GND (power), N13 VCC (power)

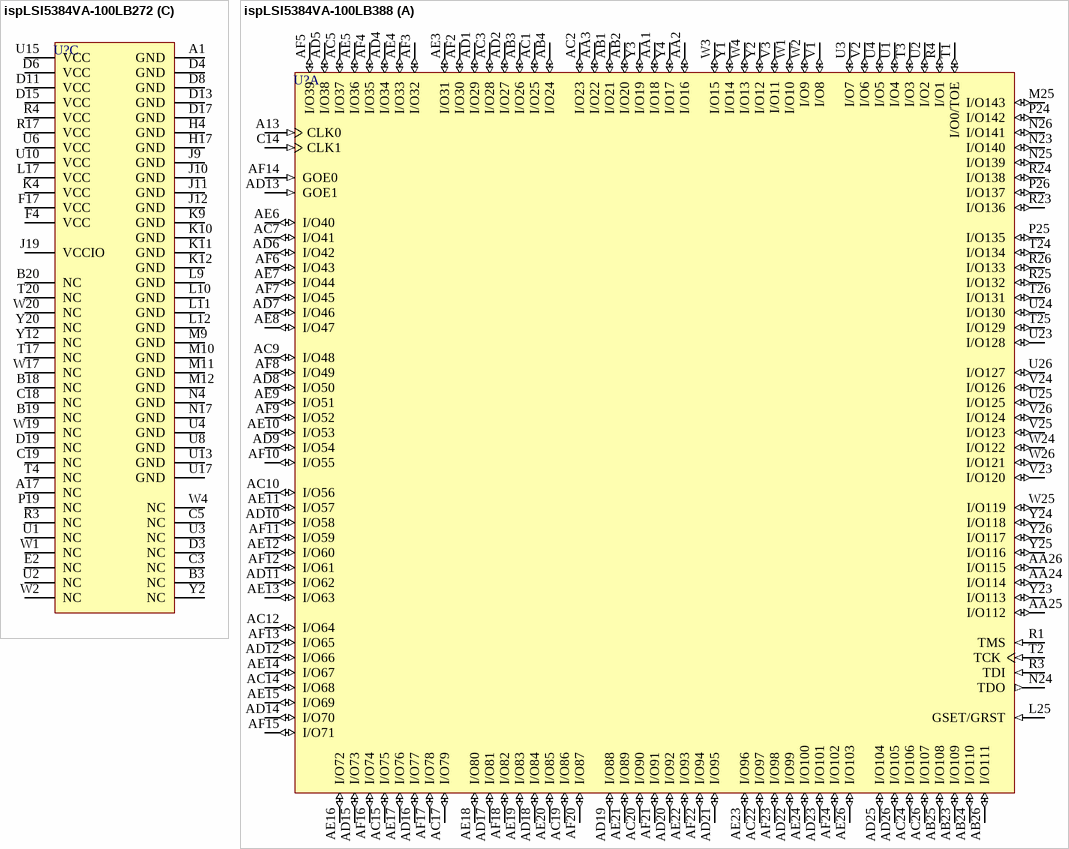
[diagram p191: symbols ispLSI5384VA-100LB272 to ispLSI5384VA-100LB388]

## ispLSI5384VA-100LB272
designator U?
In-System Programmable 3.3V SuperWIDE High Density PLD
footprint BGA272 (BGA, 272-Leads, Body 27x27mm, Pitch 1.27mm)
3D model 5384VA-BGA272 (272-Ball Ball Grid Array (BGA272))
part A pins: C10 CLK0 (in), D10 CLK1 (in), J18 GSET/GRST (in), J20 TDO (out), K17 I/O95 (io), K18 I/O94 (io), K19 I/O93 (io), K20 I/O92 (io), L3 TMS (in), L4 TCK (in), L18 I/O90 (io), L19 I/O89 (io), L20 I/O91 (io), M1 TDI (in), M2 I/O0 / TOE (io), M3 I/O1 (io), M4 I/O2 (io), M17 I/O85 (io), M18 I/O86 (io), M19 I/O87 (io), M20 I/O88 (io), N1 I/O3 (io), N2 I/O4 (io), N3 I/O5 (io), N18 I/O82 (io), N19 I/O83 (io), N20 I/O84 (io), P1 I/O6 (io), P2 I/O7 (io), P3 I/O9 (io), P4 I/O12 (io), P17 I/O77 (io), P18 I/O80 (io), P20 I/O81 (io), R1 I/O8 (io), R2 I/O10 (io), R18 I/O76 (io), R19 I/O78 (io), R20 I/O79 (io), T1 I/O11 (io), T2 I/O13 (io), T3 I/O14 (io), T18 I/O74 (io), T19 I/O75 (io), U5 I/O21 (io), U7 I/O28 (io), U9 I/O37 (io), U11 GOE1 (in), U12 I/O48 (io), U14 I/O58 (io), U16 I/O64 (io), U18 I/O71 (io), U19 I/O70 (io), U20 I/O73 (io), V1 I/O15 (io), V2 I/O16 (io), V3 I/O17 (io), V4 I/O20 (io), V5 I/O24 (io), V6 I/O27 (io), V7 I/O31 (io), V8 I/O34 (io), V9 I/O38 (io), V10 I/O42 (io), V11 GOE0 (in), V12 I/O47 (io), V13 I/O51 (io), V14 I/O55 (io), V15 I/O59 (io), V16 I/O62 (io), V17 I/O65 (io), V18 I/O68 (io), V19 I/O69 (io), V20 I/O72 (io), W3 I/O19 (io), W5 I/O25 (io), W6 I/O29 (io), W7 I/O32 (io), W8 I/O35 (io), W9 I/O39 (io), W10 I/O41 (io), W11 I/O45 (io), W12 I/O46 (io), W13 I/O50 (io), W14 I/O53 (io), W15 I/O56 (io), W16 I/O60 (io), W18 I/O66 (io), Y1 I/O18 (io), Y3 I/O22 (io), Y4 I/O23 (io), Y5 I/O26 (io), Y6 I/O30 (io), Y7 I/O33 (io), Y8 I/O36 (io), Y9 I/O40 (io), Y10 I/O43 (io), Y11 I/O44 (io), Y13 I/O49 (io), Y14 I/O52 (io), Y15 I/O54 (io), Y16 I/O57 (io), Y17 I/O61 (io), Y18 I/O63 (io), Y19 I/O67 (io)
part B pins: A2 I/O164 (io), A3 I/O160 (io), A4 I/O158 (io), A5 I/O154 (io), A6 I/O151 (io), A7 I/O149 (io), A8 I/O146 (io), A9 I/O142 (io), A10 I/O140 (io), A11 I/O139 (io), A12 I/O136 (io), A13 I/O132 (io), A14 I/O129 (io), A15 I/O126 (io), A16 I/O122 (io), A18 CLK2/I/O119 (io), A19 I/O115 (io), A20 I/O114 (io), B1 I/O165 (io), B2 I/O163 (io), B4 I/O159 (io), B5 I/O157 (io), B6 I/O153 (io), B7 I/O150 (io), B8 I/O147 (io), B9 I/O143 (io), B10 I/O141 (io), B11 I/O137 (io), B12 I/O135 (io), B13 CLK3/I/O131 (io), B14 I/O128 (io), B15 I/O125 (io), B16 I/O121 (io), B17 I/O116 (io), C1 I/O169 (io), C2 I/O166 (io), C4 I/O162 (io), C6 I/O156 (io), C7 I/O152 (io), C8 I/O148 (io), C9 I/O144 (io), C11 I/O138 (io), C12 I/O134 (io), C13 I/O130 (io), C14 I/O127 (io), C15 I/O123 (io), C16 I/O120 (io), C17 I/O117 (io), C20 I/O111 (io), D1 I/O170 (io), D2 I/O167 (io), D5 I/O161 (io), D7 I/O155 (io), D9 I/O145 (io), D12 I/O133 (io), D14 I/O124 (io), D16 I/O118 (io), D18 I/O113 (io), D20 I/O109 (io), E1 I/O172 (io), E3 I/O171 (io), E4 I/O168 (io), E17 I/O112 (io), E18 I/O110 (io), E19 I/O108 (io), E20 I/O105 (io), F1 I/O176 (io), F2 I/O175 (io), F3 I/O173 (io), F18 I/O107 (io), F19 I/O104 (io), F20 I/O102 (io), G1 I/O179 (io), G2 I/O178 (io), G3 I/O177 (io), G4 I/O174 (io), G17 I/O106 (io), G18 I/O103 (io), G19 I/O101 (io), G20 I/O100 (io), H1 I/O182 (io), H2 I/O181 (io), H3 I/O180 (io), H18 I/O99 (io), H19 I/O98 (io), H20 I/O97 (io), J1 I/O186 (io), J2 I/O185 (io), J3 I/O184 (io), J4 I/O183 (io), J17 I/O96 (io), K1 I/O189 (io), K2 I/O187 (io), K3 I/O188 (io), L1 I/O190 (io), L2 I/O191 (io)
part C pins: A1 GND (power), A17 NC, B3 NC, B18 NC, B19 NC, B20 NC, C3 NC, C5 NC, C18 NC, C19 NC, D3 NC, D4 GND (power), D6 VCC (power), D8 GND (power), D11 VCC (power), D13 GND (power), D15 VCC (power), D17 GND (power), D19 NC, E2 NC, F4 VCC (power), F17 VCC (power), H4 GND (power), H17 GND (power), J9 GND (power), J10 GND (power), J11 GND (power), J12 GND (power), J19 VCCIO (power), K4 VCC (power), K9 GND (power), K10 GND (power), K11 GND (power), K12 GND (power), L9 GND (power), L10 GND (power), L11 GND (power), L12 GND (power), L17 VCC (power), M9 GND (power), M10 GND (power), M11 GND (power), M12 GND (power), N4 GND (power), N17 GND (power), P19 NC, R3 NC, R4 VCC (power), R17 VCC (power), T4 NC, T17 NC, T20 NC, U1 NC, U2 NC, U3 NC, U4 GND (power), U6 VCC (power), U8 GND (power), U10 VCC (power), U13 GND (power), U15 VCC (power), U17 GND (power), W1 NC, W2 NC, W4 NC, W17 NC, W19 NC, W20 NC, Y2 NC, Y12 NC, Y20 NC

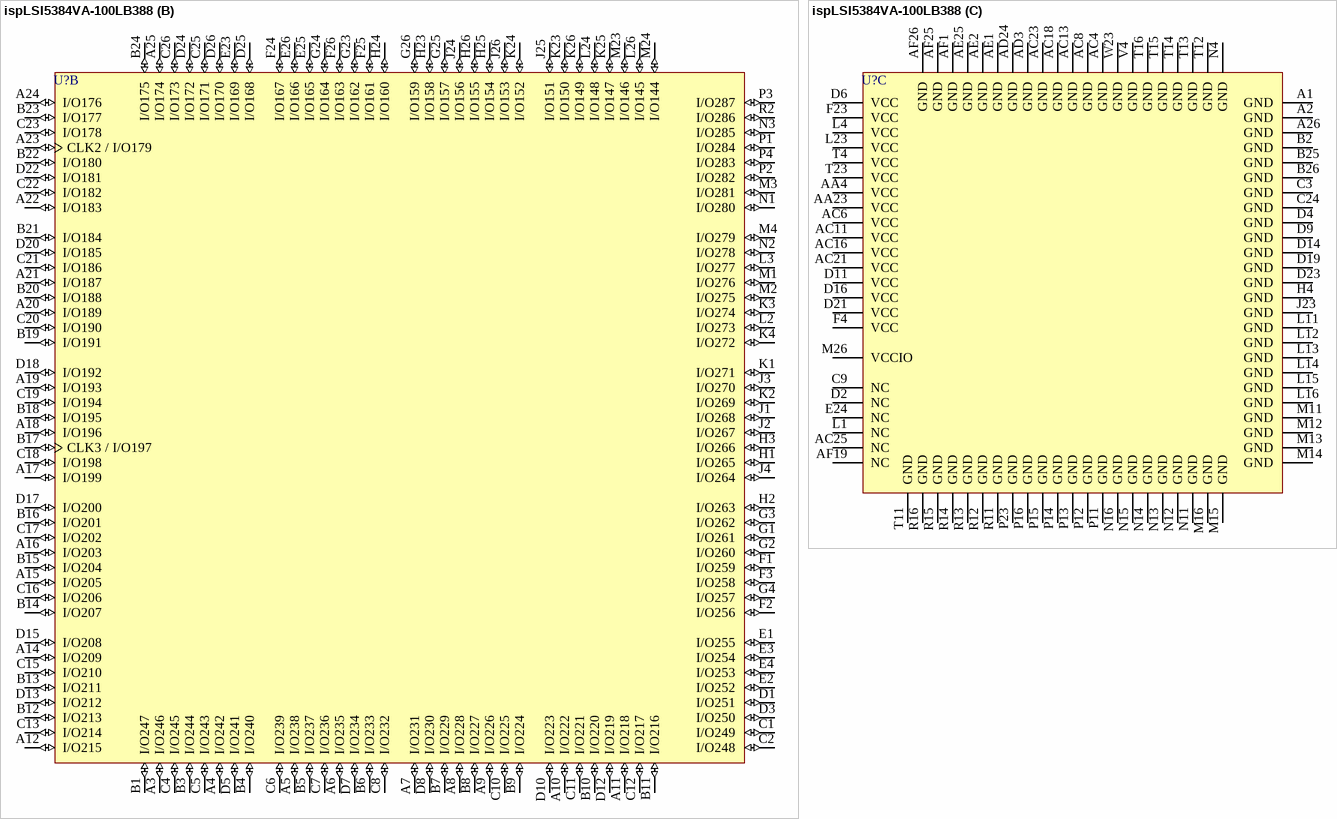
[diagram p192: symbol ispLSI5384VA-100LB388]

## ispLSI5384VA-100LB388
designator U?
In-System Programmable 3.3V SuperWIDE High Density PLD
footprint BGA388 (BGA, 388-Leads, Body 35x35mm, Pitch 1.27mm)
3D model 5384VA-BGA388 (388-Ball Ball Grid Array (BGA388))
part A pins: A13 CLK0 (in), AA1 I/O18 (io), AA2 I/O16 (io), AA3 I/O22 (io), AA24 I/O114 (io), AA25 I/O112 (io), AA26 I/O115 (io), AB1 I/O21 (io), AB2 I/O20 (io), AB3 I/O26 (io), AB4 I/O24 (io), AB23 I/O109 (io), AB24 I/O110 (io), AB25 I/O108 (io), AB26 I/O111 (io), AC1 I/O25 (io), AC2 I/O23 (io), AC3 I/O28 (io), AC5 I/O37 (io), AC7 I/O41 (io), AC9 I/O48 (io), AC10 I/O56 (io), AC12 I/O64 (io), AC14 I/O68 (io), AC15 I/O75 (io), AC17 I/O79 (io), AC19 I/O86 (io), AC20 I/O90 (io), AC22 I/O97 (io), AC24 I/O106 (io), AC26 I/O107 (io), AD1 I/O29 (io), AD2 I/O27 (io), AD4 I/O34 (io), AD5 I/O38 (io), AD6 I/O42 (io), AD7 I/O46 (io), AD8 I/O50 (io), AD9 I/O54 (io), AD10 I/O58 (io), AD11 I/O62 (io), AD12 I/O66 (io), AD13 GOE1 (in), AD14 I/O70 (io), AD15 I/O73 (io), AD16 I/O77 (io), AD17 I/O81 (io), AD18 I/O84 (io), AD19 I/O88 (io), AD20 I/O92 (io), AD21 I/O95 (io), AD22 I/O99 (io), AD23 I/O101 (io), AD25 I/O104 (io), AD26 I/O105 (io), AE3 I/O31 (io), AE4 I/O33 (io), AE5 I/O36 (io), AE6 I/O40 (io), AE7 I/O44 (io), AE8 I/O47 (io), AE9 I/O51 (io), AE10 I/O53 (io), AE11 I/O57 (io), AE12 I/O60 (io), AE13 I/O63 (io), AE14 I/O67 (io), AE15 I/O69 (io), AE16 I/O72 (io), AE17 I/O76 (io), AE18 I/O80 (io), AE19 I/O83 (io), AE20 I/O85 (io), AE21 I/O89 (io), AE22 I/O93 (io), AE23 I/O96 (io), AE24 I/O100 (io), AE26 I/O103 (io), AF2 I/O30 (io), AF3 I/O32 (io), AF4 I/O35 (io), AF5 I/O39 (io), AF6 I/O43 (io), AF7 I/O45 (io), AF8 I/O49 (io), AF9 I/O52 (io), AF10 I/O55 (io), AF11 I/O59 (io), AF12 I/O61 (io), AF13 I/O65 (io), AF14 GOE0 (in), AF15 I/O71 (io), AF16 I/O74 (io), AF17 I/O78 (io), AF18 I/O82 (io), AF20 I/O87 (io), AF21 I/O91 (io), AF22 I/O94 (io), AF23 I/O98 (io), AF24 I/O102 (io), C14 CLK1 (in), L25 GSET/GRST (in), M25 I/O143 (io), N23 I/O140 (io), N24 TDO (out), N25 I/O139 (io), N26 I/O141 (io), P24 I/O142 (io), P25 I/O135 (io), P26 I/O137 (io), R1 TMS (in), R3 TDI (in), R4 I/O1 (io), R23 I/O136 (io), R24 I/O138 (io), R25 I/O132 (io), R26 I/O133 (io), T1 I/O0/TOE (io), T2 TCK (in), T3 I/O3 (io), T24 I/O134 (io), T25 I/O129 (io), T26 I/O131 (io), U1 I/O4 (io), U2 I/O2 (io), U3 I/O7 (io), U4 I/O5 (io), U23 I/O128 (io), U24 I/O130 (io), U25 I/O125 (io), U26 I/O127 (io), V1 I/O8 (io), V2 I/O6 (io), V3 I/O11 (io), V23 I/O120 (io), V24 I/O126 (io), V25 I/O123 (io), V26 I/O124 (io), W1 I/O10 (io), W2 I/O9 (io), W3 I/O15 (io), W4 I/O13 (io), W24 I/O122 (io), W25 I/O119 (io), W26 I/O121 (io), Y1 I/O14 (io), Y2 I/O12 (io), Y3 I/O19 (io), Y4 I/O17 (io), Y23 I/O113 (io), Y24 I/O118 (io), Y25 I/O116 (io), Y26 I/O117 (io)
part B pins: A3 I/O246 (io), A4 I/O242 (io), A5 I/O238 (io), A6 I/O235 (io), A7 I/O231 (io), A8 I/O228 (io), A9 I/O226 (io), A10 I/O222 (io), A11 I/O218 (io), A12 I/O215 (io), A14 I/O209 (io), A15 I/O205 (io), A16 I/O203 (io), A17 I/O199 (io), A18 I/O196 (io), A19 I/O193 (io), A20 I/O189 (io), A21 I/O187 (io), A22 I/O183 (io), A23 CLK2 / I/O179 (io), A24 I/O176 (io), A25 I/O174 (io), B1 I/O247 (io), B3 I/O244 (io), B4 I/O240 (io), B5 I/O237 (io), B6 I/O233 (io), B7 I/O229 (io), B8 I/O227 (io), B9 I/O224 (io), B10 I/O220 (io), B11 I/O216 (io), B12 I/O213 (io), B13 I/O211 (io), B14 I/O207 (io), B15 I/O204 (io), B16 I/O201 (io), B17 CLK3 / I/O197 (io), B18 I/O195 (io), B19 I/O191 (io), B20 I/O188 (io), B21 I/O184 (io), B22 I/O180 (io), B23 I/O177 (io), B24 I/O175 (io), C1 I/O249 (io), C2 I/O248 (io), C4 I/O245 (io), C5 I/O243 (io), C6 I/O239 (io), C7 I/O236 (io), C8 I/O232 (io), C10 I/O225 (io), C11 I/O221 (io), C12 I/O217 (io), C13 I/O214 (io), C15 I/O210 (io), C16 I/O206 (io), C17 I/O202 (io), C18 I/O198 (io), C19 I/O194 (io), C20 I/O190 (io), C21 I/O186 (io), C22 I/O182 (io), C23 I/O178 (io), C25 I/O171 (io), C26 I/O173 (io), D1 I/O251 (io), D3 I/O250 (io), D5 I/O241 (io), D7 I/O234 (io), D8 I/O230 (io), D10 I/O223 (io), D12 I/O219 (io), D13 I/O212 (io), D15 I/O208 (io), D17 I/O200 (io), D18 I/O192 (io), D20 I/O185 (io), D22 I/O181 (io), D24 I/O172 (io), D25 I/O168 (io), D26 I/O170 (io), E1 I/O255 (io), E2 I/O252 (io), E3 I/O254 (io), E4 I/O253 (io), E23 I/O169 (io), E25 I/O165 (io), E26 I/O166 (io), F1 I/O259 (io), F2 I/O256 (io), F3 I/O258 (io), F24 I/O167 (io), F25 I/O161 (io), F26 I/O163 (io), G1 I/O261 (io), G2 I/O260 (io), G3 I/O262 (io), G4 I/O257 (io), G23 I/O162 (io), G24 I/O164 (io), G25 I/O157 (io), G26 I/O159 (io), H1 I/O265 (io), H2 I/O263 (io), H3 I/O266 (io), H23 I/O158 (io), H24 I/O160 (io), H25 I/O154 (io), H26 I/O155 (io), J1 I/O268 (io), J2 I/O267 (io), J3 I/O270 (io), J4 I/O264 (io), J24 I/O156 (io), J25 I/O151 (io), J26 I/O153 (io), K1 I/O271 (io), K2 I/O269 (io), K3 I/O274 (io), K4 I/O272 (io), K23 I/O150 (io), K24 I/O152 (io), K25 I/O147 (io), K26 I/O149 (io), L2 I/O273 (io), L3 I/O277 (io), L24 I/O148 (io), L26 I/O145 (io), M1 I/O276 (io), M2 I/O275 (io), M3 I/O281 (io), M4 I/O279 (io), M23 I/O146 (io), M24 I/O144 (io), N1 I/O280 (io), N2 I/O278 (io), N3 I/O285 (io), P1 I/O284 (io), P2 I/O282 (io), P3 I/O287 (io), P4 I/O283 (io), R2 I/O286 (io)
part C pins: A1 GND (power), A2 GND (power), A26 GND (power), AA4 VCC (power), AA23 VCC (power), AC4 GND (power), AC6 VCC (power), AC8 GND (power), AC11 VCC (power), AC13 GND (power), AC16 VCC (power), AC18 GND (power), AC21 VCC (power), AC23 GND (power), AC25 NC, AD3 GND (power), AD24 GND (power), AE1 GND (power), AE2 GND (power), AE25 GND (power), AF1 GND (power), AF19 NC, AF25 GND (power), AF26 GND (power), B2 GND (power), B25 GND (power), B26 GND (power), C3 GND (power), C9 NC, C24 GND (power), D2 NC, D4 GND (power), D6 VCC (power), D9 GND (power), D11 VCC (power), D14 GND (power), D16 VCC (power), D19 GND (power), D21 VCC (power), D23 GND (power), E24 NC, F4 VCC (power), F23 VCC (power), H4 GND (power), J23 GND (power), L1 NC, L4 VCC (power), L11 GND (power), L12 GND (power), L13 GND (power), L14 GND (power), L15 GND (power), L16 GND (power), L23 VCC (power), M11 GND (power), M12 GND (power), M13 GND (power), M14 GND (power), M15 GND (power), M16 GND (power), M26 VCCIO (power), N4 GND (power), N11 GND (power), N12 GND (power), N13 GND (power), N14 GND (power), N15 GND (power), N16 GND (power), P11 GND (power), P12 GND (power), P13 GND (power), P14 GND (power), P15 GND (power), P16 GND (power), P23 GND (power), R11 GND (power), R12 GND (power), R13 GND (power), R14 GND (power), R15 GND (power), R16 GND (power), T4 VCC (power), T11 GND (power), T12 GND (power), T13 GND (power), T14 GND (power), T15 GND (power), T16 GND (power), T23 VCC (power), V4 GND (power), W23 GND (power)

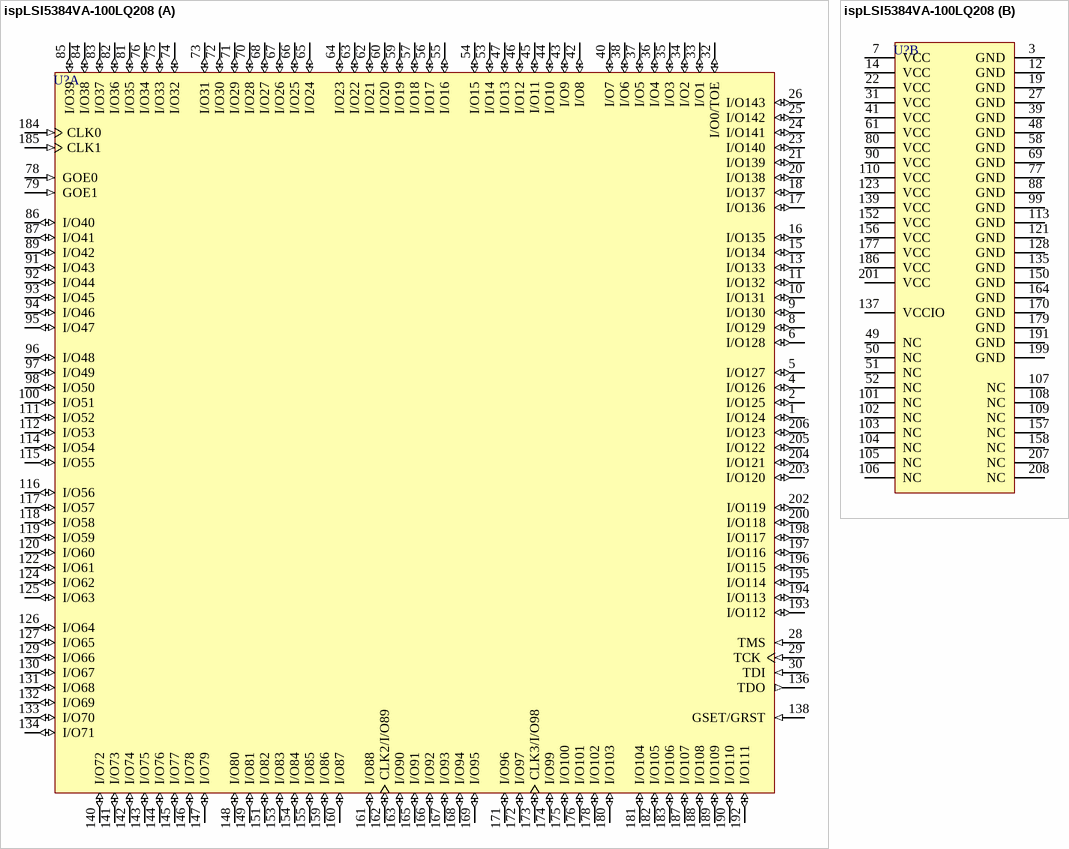
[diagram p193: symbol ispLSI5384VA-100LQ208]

## ispLSI5384VA-100LQ208
designator U?
In-System Programmable 3.3V SuperWIDE High Density PLD
footprint PQFP208_N (Shrink QFP, 208-Leads, Body 28x28mm, Pitch 0.5mm, IPC Medium Density)
footprint PQFP208_L (Shrink QFP, 208-Leads, Body 28x28mm, Pitch 0.5mm, IPC High Density)
footprint PQFP208_M (Shrink QFP, 208-Leads, Body 28x28mm, Pitch 0.5mm, IPC Low Density)
3D model 5384VA-PQFP208 (208-Pin Plastic Quad Flat Pack (PQFP208))
part A pins: 1 I/O124 (io), 2 I/O125 (io), 4 I/O126 (io), 5 I/O127 (io), 6 I/O128 (io), 8 I/O129 (io), 9 I/O130 (io), 10 I/O131 (io), 11 I/O132 (io), 13 I/O133 (io), 15 I/O134 (io), 16 I/O135 (io), 17 I/O136 (io), 18 I/O137 (io), 20 I/O138 (io), 21 I/O139 (io), 23 I/O140 (io), 24 I/O141 (io), 25 I/O142 (io), 26 I/O143 (io), 28 TMS (in), 29 TCK (in), 30 TDI (in), 32 I/O0/TOE (io), 33 I/O1 (io), 34 I/O2 (io), 35 I/O3 (io), 36 I/O4 (io), 37 I/O5 (io), 38 I/O6 (io), 40 I/O7 (io), 42 I/O8 (io), 43 I/O9 (io), 44 I/O10 (io), 45 I/O11 (io), 46 I/O12 (io), 47 I/O13 (io), 53 I/O14 (io), 54 I/O15 (io), 55 I/O16 (io), 56 I/O17 (io), 57 I/O18 (io), 59 I/O19 (io), 60 I/O20 (io), 62 I/O21 (io), 63 I/O22 (io), 64 I/O23 (io), 65 I/O24 (io), 66 I/O25 (io), 67 I/O26 (io), 68 I/O27 (io), 70 I/O28 (io), 71 I/O29 (io), 72 I/O30 (io), 73 I/O31 (io), 74 I/O32 (io), 75 I/O33 (io), 76 I/O34 (io), 78 GOE0 (in), 79 GOE1 (in), 81 I/O35 (io), 82 I/O36 (io), 83 I/O37 (io), 84 I/O38 (io), 85 I/O39 (io), 86 I/O40 (io), 87 I/O41 (io), 89 I/O42 (io), 91 I/O43 (io), 92 I/O44 (io), 93 I/O45 (io), 94 I/O46 (io), 95 I/O47 (io), 96 I/O48 (io), 97 I/O49 (io), 98 I/O50 (io), 100 I/O51 (io), 111 I/O52 (io), 112 I/O53 (io), 114 I/O54 (io), 115 I/O55 (io), 116 I/O56 (io), 117 I/O57 (io), 118 I/O58 (io), 119 I/O59 (io), 120 I/O60 (io), 122 I/O61 (io), 124 I/O62 (io), 125 I/O63 (io), 126 I/O64 (io), 127 I/O65 (io), 129 I/O66 (io), 130 I/O67 (io), 131 I/O68 (io), 132 I/O69 (io), 133 I/O70 (io), 134 I/O71 (io), 136 TDO (out), 138 GSET/GRST (in), 140 I/O72 (io), 141 I/O73 (io), 142 I/O74 (io), 143 I/O75 (io), 144 I/O76 (io), 145 I/O77 (io), 146 I/O78 (io), 147 I/O79 (io), 148 I/O80 (io), 149 I/O81 (io), 151 I/O82 (io), 153 I/O83 (io), 154 I/O84 (io), 155 I/O85 (io), 159 I/O86 (io), 160 I/O87 (io), 161 I/O88 (io), 162 CLK2/I/O89 (io), 163 I/O90 (io), 165 I/O91 (io), 166 I/O92 (io), 167 I/O93 (io), 168 I/O94 (io), 169 I/O95 (io), 171 I/O96 (io), 172 I/O97 (io), 173 CLK3/I/O98 (io), 174 I/O99 (io), 175 I/O100 (io), 176 I/O101 (io), 178 I/O102 (io), 180 I/O103 (io), 181 I/O104 (io), 182 I/O105 (io), 183 I/O106 (io), 184 CLK0 (in), 185 CLK1 (in), 187 I/O107 (io), 188 I/O108 (io), 189 I/O109 (io), 190 I/O110 (io), 192 I/O111 (io), 193 I/O112 (io), 194 I/O113 (io), 195 I/O114 (io), 196 I/O115 (io), 197 I/O116 (io), 198 I/O117 (io), 200 I/O118 (io), 202 I/O119 (io), 203 I/O120 (io), 204 I/O121 (io), 205 I/O122 (io), 206 I/O123 (io)
part B pins: 3 GND (power), 7 VCC (power), 12 GND (power), 14 VCC (power), 19 GND (power), 22 VCC (power), 27 GND (power), 31 VCC (power), 39 GND (power), 41 VCC (power), 48 GND (power), 49 NC, 50 NC, 51 NC, 52 NC, 58 GND (power), 61 VCC (power), 69 GND (power), 77 GND (power), 80 VCC (power), 88 GND (power), 90 VCC (power), 99 GND (power), 101 NC, 102 NC, 103 NC, 104 NC, 105 NC, 106 NC, 107 NC, 108 NC, 109 NC, 110 VCC (power), 113 GND (power), 121 GND (power), 123 VCC (power), 128 GND (power), 135 GND (power), 137 VCCIO (power), 139 VCC (power), 150 GND (power), 152 VCC (power), 156 VCC (power), 157 NC, 158 NC, 164 GND (power), 170 GND (power), 177 VCC (power), 179 GND (power), 186 VCC (power), 191 GND (power), 199 GND (power), 201 VCC (power), 207 NC, 208 NC

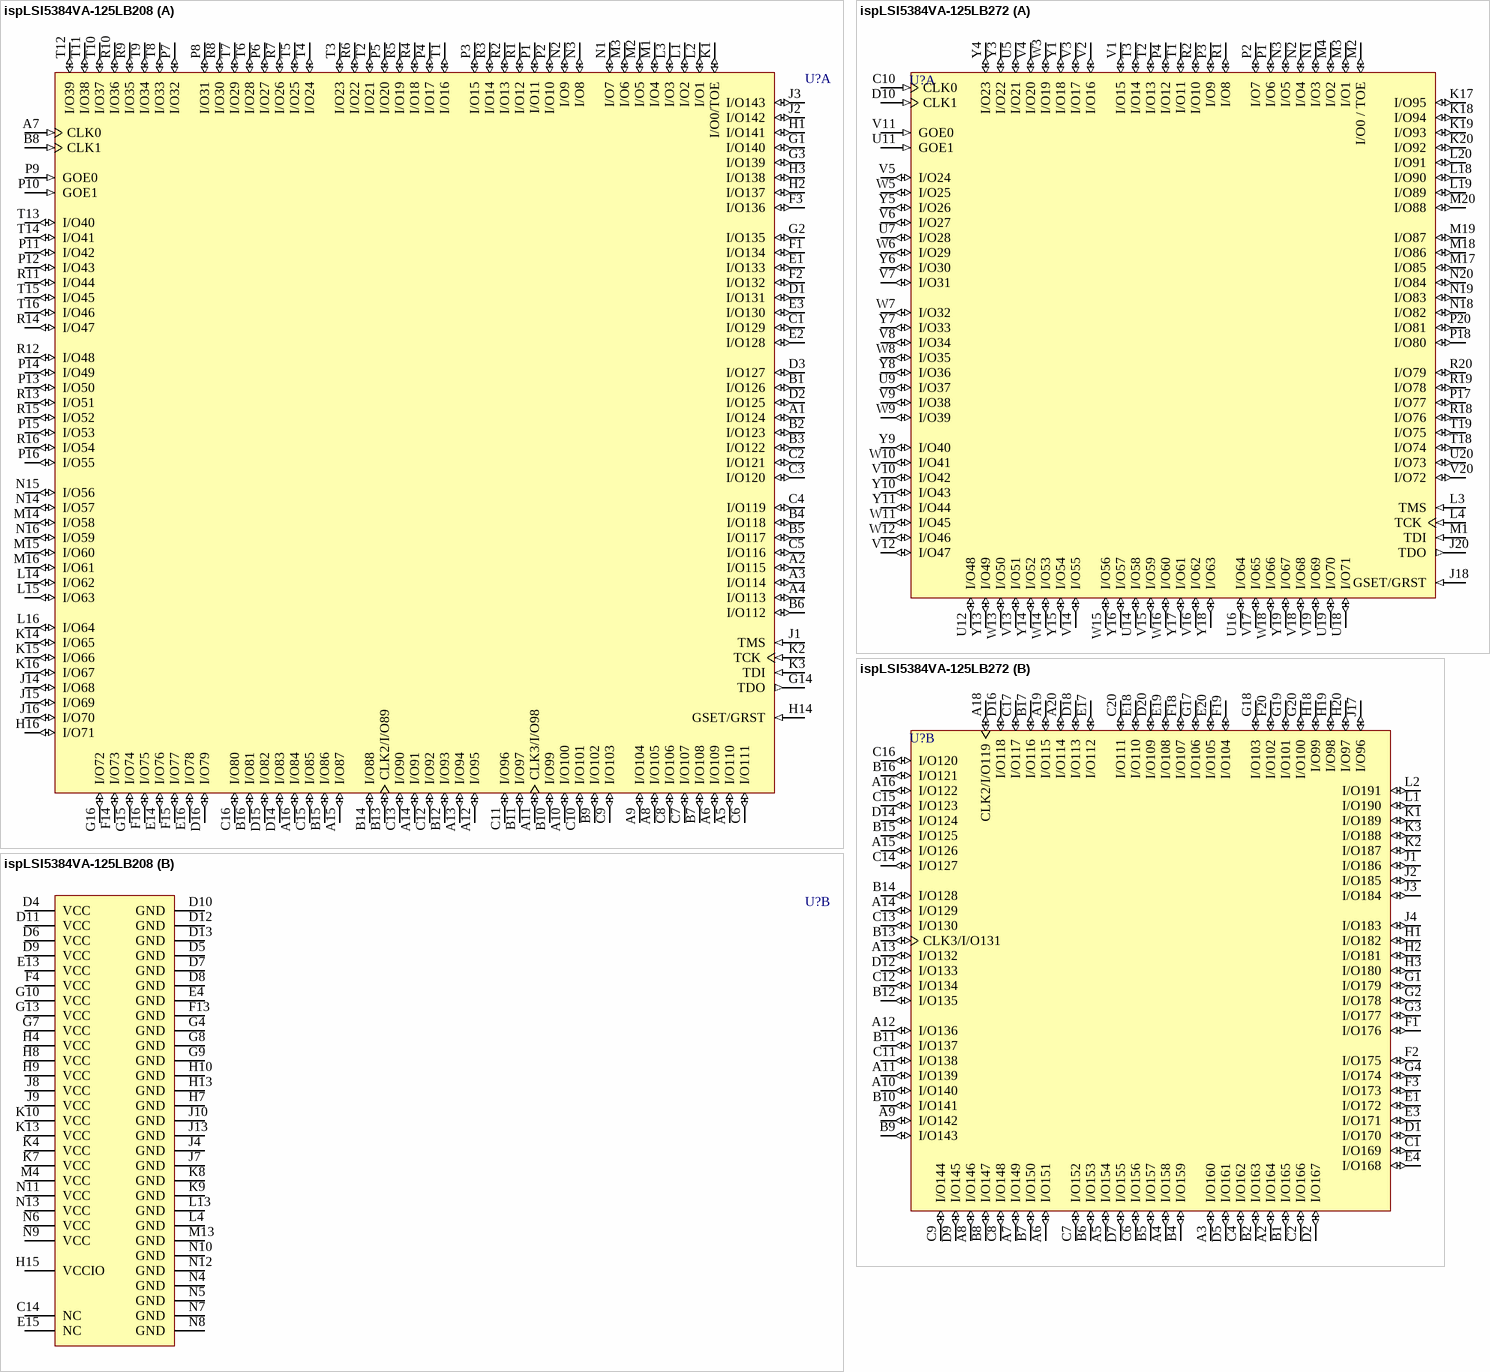
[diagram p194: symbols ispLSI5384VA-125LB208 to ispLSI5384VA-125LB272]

## ispLSI5384VA-125LB208
designator U?
In-System Programmable 3.3V SuperWIDE High Density PLD
footprint fpBGA208 (BGA, 208-Leads, Body 17x17mm, Pitch 1mm)
3D model 5256VA-fpBGA208 (208-Ball Fine Pitch Ball Grid Array (fpBGA208))
part A pins: A1 I/O124 (io), A2 I/O115 (io), A3 I/O114 (io), A4 I/O113 (io), A5 I/O110 (io), A6 I/O109 (io), A7 CLK0 (in), A8 I/O105 (io), A9 I/O104 (io), A10 I/O100 (io), A11 CLK3/I/O98 (io), A12 I/O95 (io), A13 I/O94 (io), A14 I/O91 (io), A15 I/O87 (io), A16 I/O84 (io), B1 I/O126 (io), B2 I/O123 (io), B3 I/O122 (io), B4 I/O118 (io), B5 I/O117 (io), B6 I/O112 (io), B7 I/O108 (io), B8 CLK1 (in), B9 I/O102 (io), B10 I/O99 (io), B11 I/O97 (io), B12 I/O93 (io), B13 CLK2/I/O89 (io), B14 I/O88 (io), B15 I/O86 (io), B16 I/O81 (io), C1 I/O129 (io), C2 I/O121 (io), C3 I/O120 (io), C4 I/O119 (io), C5 I/O116 (io), C6 I/O111 (io), C7 I/O107 (io), C8 I/O106 (io), C9 I/O103 (io), C10 I/O101 (io), C11 I/O96 (io), C12 I/O92 (io), C13 I/O90 (io), C15 I/O85 (io), C16 I/O80 (io), D1 I/O131 (io), D2 I/O125 (io), D3 I/O127 (io), D14 I/O83 (io), D15 I/O82 (io), D16 I/O79 (io), E1 I/O133 (io), E2 I/O128 (io), E3 I/O130 (io), E14 I/O76 (io), E16 I/O78 (io), F1 I/O134 (io), F2 I/O132 (io), F3 I/O136 (io), F14 I/O73 (io), F15 I/O77 (io), F16 I/O75 (io), G1 I/O140 (io), G2 I/O135 (io), G3 I/O139 (io), G14 TDO (out), G15 I/O74 (io), G16 I/O72 (io), H1 I/O141 (io), H2 I/O137 (io), H3 I/O138 (io), H14 GSET/GRST (in), H16 I/O71 (io), J1 TMS (in), J2 I/O142 (io), J3 I/O143 (io), J14 I/O68 (io), J15 I/O69 (io), J16 I/O70 (io), K1 I/O0/TOE (io), K2 TCK (in), K3 TDI (in), K14 I/O65 (io), K15 I/O66 (io), K16 I/O67 (io), L1 I/O2 (io), L2 I/O1 (io), L3 I/O3 (io), L14 I/O62 (io), L15 I/O63 (io), L16 I/O64 (io), M1 I/O4 (io), M2 I/O5 (io), M3 I/O6 (io), M14 I/O58 (io), M15 I/O60 (io), M16 I/O61 (io), N1 I/O7 (io), N2 I/O9 (io), N3 I/O8 (io), N14 I/O57 (io), N15 I/O56 (io), N16 I/O59 (io), P1 I/O11 (io), P2 I/O10 (io), P3 I/O15 (io), P4 I/O17 (io), P5 I/O20 (io), P6 I/O27 (io), P7 I/O32 (io), P8 I/O31 (io), P9 GOE0 (in), P10 GOE1 (in), P11 I/O42 (io), P12 I/O43 (io), P13 I/O50 (io), P14 I/O49 (io), P15 I/O53 (io), P16 I/O55 (io), R1 I/O12 (io), R2 I/O13 (io), R3 I/O14 (io), R4 I/O18 (io), R5 I/O19 (io), R6 I/O22 (io), R7 I/O26 (io), R8 I/O30 (io), R9 I/O35 (io), R10 I/O36 (io), R11 I/O44 (io), R12 I/O48 (io), R13 I/O51 (io), R14 I/O47 (io), R15 I/O52 (io), R16 I/O54 (io), T1 I/O16 (io), T2 I/O21 (io), T3 I/O23 (io), T4 I/O24 (io), T5 I/O25 (io), T6 I/O28 (io), T7 I/O29 (io), T8 I/O33 (io), T9 I/O34 (io), T10 I/O37 (io), T11 I/O38 (io), T12 I/O39 (io), T13 I/O40 (io), T14 I/O41 (io), T15 I/O45 (io), T16 I/O46 (io)
part B pins: C14 NC, D4 VCC (power), D5 GND (power), D6 VCC (power), D7 GND (power), D8 GND (power), D9 VCC (power), D10 GND (power), D11 VCC (power), D12 GND (power), D13 GND (power), E4 GND (power), E13 VCC (power), E15 NC, F4 VCC (power), F13 GND (power), G4 GND (power), G7 VCC (power), G8 GND (power), G9 GND (power), G10 VCC (power), G13 VCC (power), H4 VCC (power), H7 GND (power), H8 VCC (power), H9 VCC (power), H10 GND (power), H13 GND (power), H15 VCCIO (power), J4 GND (power), J7 GND (power), J8 VCC (power), J9 VCC (power), J10 GND (power), J13 GND (power), K4 VCC (power), K7 VCC (power), K8 GND (power), K9 GND (power), K10 VCC (power), K13 VCC (power), L4 GND (power), L13 GND (power), M4 VCC (power), M13 GND (power), N4 GND (power), N5 GND (power), N6 VCC (power), N7 GND (power), N8 GND (power), N9 VCC (power), N10 GND (power), N11 VCC (power), N12 GND (power), N13 VCC (power)

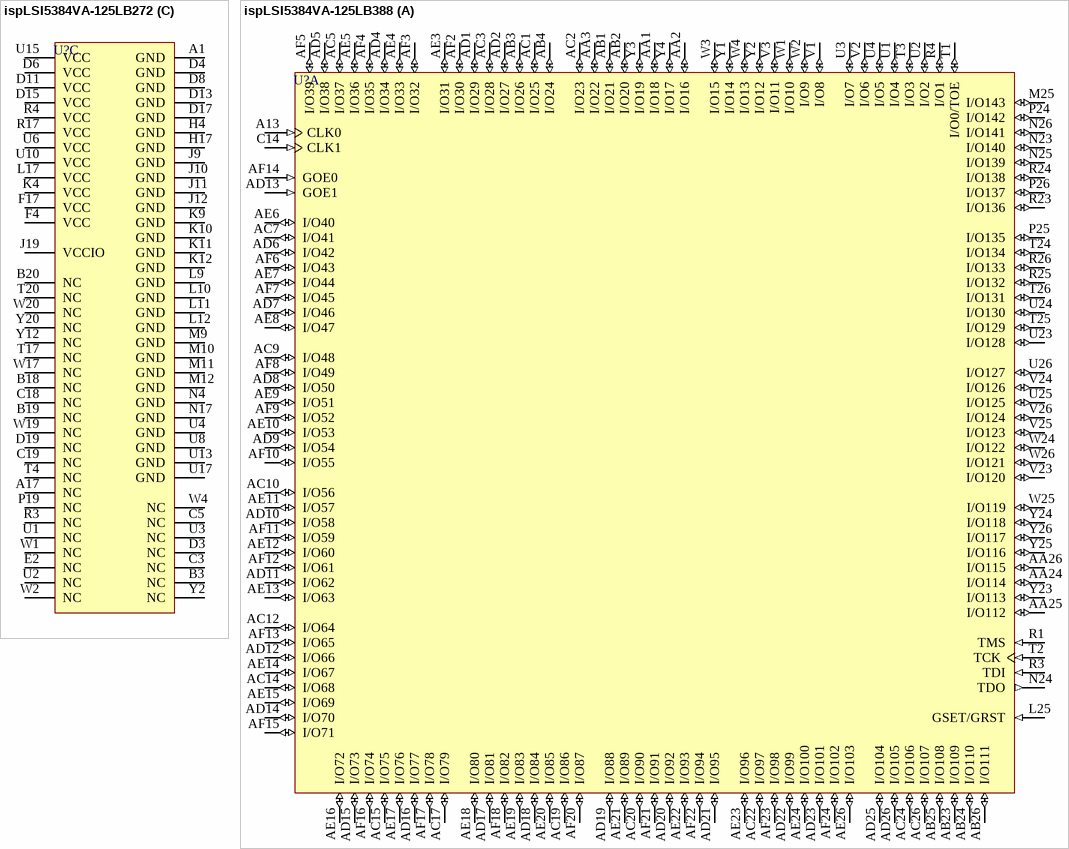
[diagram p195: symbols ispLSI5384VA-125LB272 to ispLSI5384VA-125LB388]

## ispLSI5384VA-125LB272
designator U?
In-System Programmable 3.3V SuperWIDE High Density PLD
footprint BGA272 (BGA, 272-Leads, Body 27x27mm, Pitch 1.27mm)
3D model 5384VA-BGA272 (272-Ball Ball Grid Array (BGA272))
part A pins: C10 CLK0 (in), D10 CLK1 (in), J18 GSET/GRST (in), J20 TDO (out), K17 I/O95 (io), K18 I/O94 (io), K19 I/O93 (io), K20 I/O92 (io), L3 TMS (in), L4 TCK (in), L18 I/O90 (io), L19 I/O89 (io), L20 I/O91 (io), M1 TDI (in), M2 I/O0 / TOE (io), M3 I/O1 (io), M4 I/O2 (io), M17 I/O85 (io), M18 I/O86 (io), M19 I/O87 (io), M20 I/O88 (io), N1 I/O3 (io), N2 I/O4 (io), N3 I/O5 (io), N18 I/O82 (io), N19 I/O83 (io), N20 I/O84 (io), P1 I/O6 (io), P2 I/O7 (io), P3 I/O9 (io), P4 I/O12 (io), P17 I/O77 (io), P18 I/O80 (io), P20 I/O81 (io), R1 I/O8 (io), R2 I/O10 (io), R18 I/O76 (io), R19 I/O78 (io), R20 I/O79 (io), T1 I/O11 (io), T2 I/O13 (io), T3 I/O14 (io), T18 I/O74 (io), T19 I/O75 (io), U5 I/O21 (io), U7 I/O28 (io), U9 I/O37 (io), U11 GOE1 (in), U12 I/O48 (io), U14 I/O58 (io), U16 I/O64 (io), U18 I/O71 (io), U19 I/O70 (io), U20 I/O73 (io), V1 I/O15 (io), V2 I/O16 (io), V3 I/O17 (io), V4 I/O20 (io), V5 I/O24 (io), V6 I/O27 (io), V7 I/O31 (io), V8 I/O34 (io), V9 I/O38 (io), V10 I/O42 (io), V11 GOE0 (in), V12 I/O47 (io), V13 I/O51 (io), V14 I/O55 (io), V15 I/O59 (io), V16 I/O62 (io), V17 I/O65 (io), V18 I/O68 (io), V19 I/O69 (io), V20 I/O72 (io), W3 I/O19 (io), W5 I/O25 (io), W6 I/O29 (io), W7 I/O32 (io), W8 I/O35 (io), W9 I/O39 (io), W10 I/O41 (io), W11 I/O45 (io), W12 I/O46 (io), W13 I/O50 (io), W14 I/O53 (io), W15 I/O56 (io), W16 I/O60 (io), W18 I/O66 (io), Y1 I/O18 (io), Y3 I/O22 (io), Y4 I/O23 (io), Y5 I/O26 (io), Y6 I/O30 (io), Y7 I/O33 (io), Y8 I/O36 (io), Y9 I/O40 (io), Y10 I/O43 (io), Y11 I/O44 (io), Y13 I/O49 (io), Y14 I/O52 (io), Y15 I/O54 (io), Y16 I/O57 (io), Y17 I/O61 (io), Y18 I/O63 (io), Y19 I/O67 (io)
part B pins: A2 I/O164 (io), A3 I/O160 (io), A4 I/O158 (io), A5 I/O154 (io), A6 I/O151 (io), A7 I/O149 (io), A8 I/O146 (io), A9 I/O142 (io), A10 I/O140 (io), A11 I/O139 (io), A12 I/O136 (io), A13 I/O132 (io), A14 I/O129 (io), A15 I/O126 (io), A16 I/O122 (io), A18 CLK2/I/O119 (io), A19 I/O115 (io), A20 I/O114 (io), B1 I/O165 (io), B2 I/O163 (io), B4 I/O159 (io), B5 I/O157 (io), B6 I/O153 (io), B7 I/O150 (io), B8 I/O147 (io), B9 I/O143 (io), B10 I/O141 (io), B11 I/O137 (io), B12 I/O135 (io), B13 CLK3/I/O131 (io), B14 I/O128 (io), B15 I/O125 (io), B16 I/O121 (io), B17 I/O116 (io), C1 I/O169 (io), C2 I/O166 (io), C4 I/O162 (io), C6 I/O156 (io), C7 I/O152 (io), C8 I/O148 (io), C9 I/O144 (io), C11 I/O138 (io), C12 I/O134 (io), C13 I/O130 (io), C14 I/O127 (io), C15 I/O123 (io), C16 I/O120 (io), C17 I/O117 (io), C20 I/O111 (io), D1 I/O170 (io), D2 I/O167 (io), D5 I/O161 (io), D7 I/O155 (io), D9 I/O145 (io), D12 I/O133 (io), D14 I/O124 (io), D16 I/O118 (io), D18 I/O113 (io), D20 I/O109 (io), E1 I/O172 (io), E3 I/O171 (io), E4 I/O168 (io), E17 I/O112 (io), E18 I/O110 (io), E19 I/O108 (io), E20 I/O105 (io), F1 I/O176 (io), F2 I/O175 (io), F3 I/O173 (io), F18 I/O107 (io), F19 I/O104 (io), F20 I/O102 (io), G1 I/O179 (io), G2 I/O178 (io), G3 I/O177 (io), G4 I/O174 (io), G17 I/O106 (io), G18 I/O103 (io), G19 I/O101 (io), G20 I/O100 (io), H1 I/O182 (io), H2 I/O181 (io), H3 I/O180 (io), H18 I/O99 (io), H19 I/O98 (io), H20 I/O97 (io), J1 I/O186 (io), J2 I/O185 (io), J3 I/O184 (io), J4 I/O183 (io), J17 I/O96 (io), K1 I/O189 (io), K2 I/O187 (io), K3 I/O188 (io), L1 I/O190 (io), L2 I/O191 (io)
part C pins: A1 GND (power), A17 NC, B3 NC, B18 NC, B19 NC, B20 NC, C3 NC, C5 NC, C18 NC, C19 NC, D3 NC, D4 GND (power), D6 VCC (power), D8 GND (power), D11 VCC (power), D13 GND (power), D15 VCC (power), D17 GND (power), D19 NC, E2 NC, F4 VCC (power), F17 VCC (power), H4 GND (power), H17 GND (power), J9 GND (power), J10 GND (power), J11 GND (power), J12 GND (power), J19 VCCIO (power), K4 VCC (power), K9 GND (power), K10 GND (power), K11 GND (power), K12 GND (power), L9 GND (power), L10 GND (power), L11 GND (power), L12 GND (power), L17 VCC (power), M9 GND (power), M10 GND (power), M11 GND (power), M12 GND (power), N4 GND (power), N17 GND (power), P19 NC, R3 NC, R4 VCC (power), R17 VCC (power), T4 NC, T17 NC, T20 NC, U1 NC, U2 NC, U3 NC, U4 GND (power), U6 VCC (power), U8 GND (power), U10 VCC (power), U13 GND (power), U15 VCC (power), U17 GND (power), W1 NC, W2 NC, W4 NC, W17 NC, W19 NC, W20 NC, Y2 NC, Y12 NC, Y20 NC

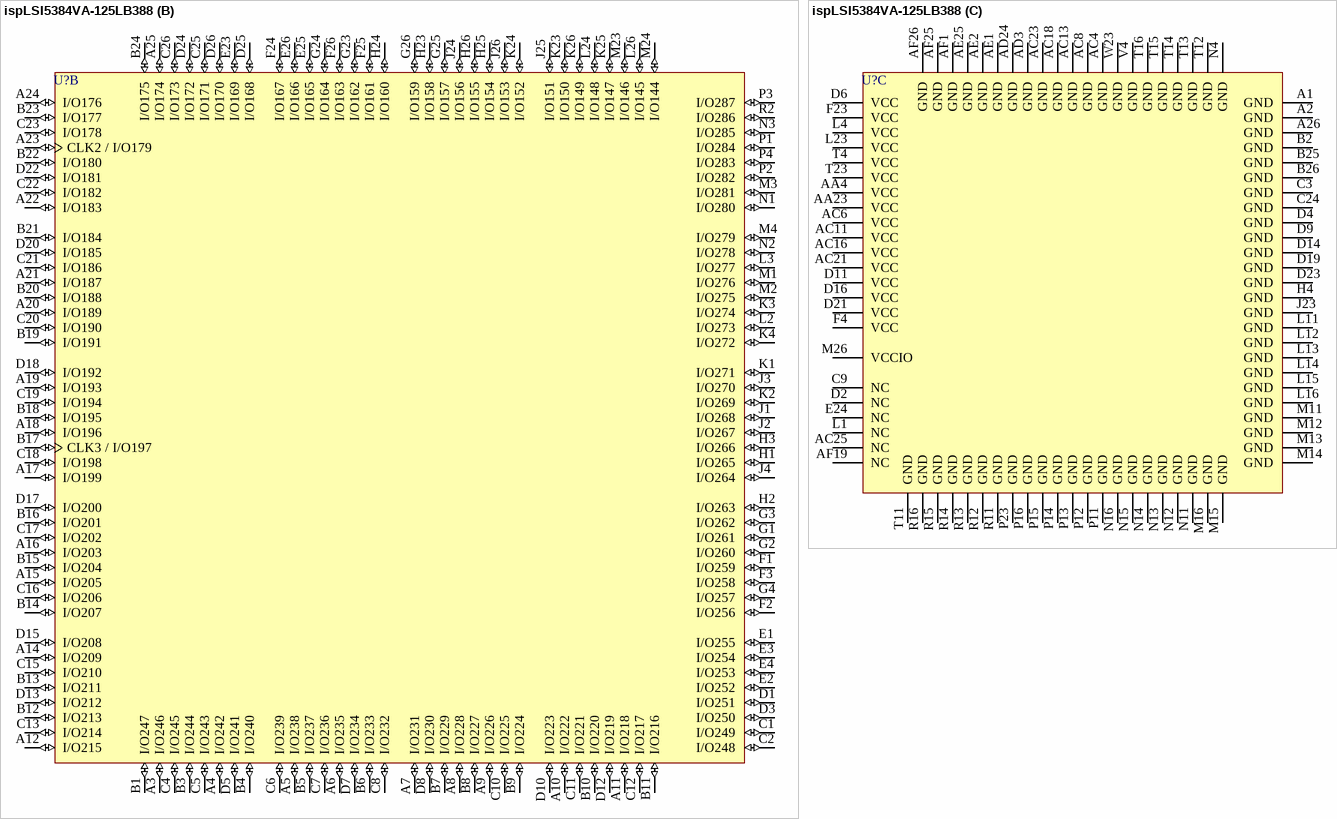
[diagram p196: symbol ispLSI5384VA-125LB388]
